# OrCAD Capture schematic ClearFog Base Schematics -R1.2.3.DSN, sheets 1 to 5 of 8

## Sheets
1 BOM Extraction: title: BOM Extraction; rev: 1.0
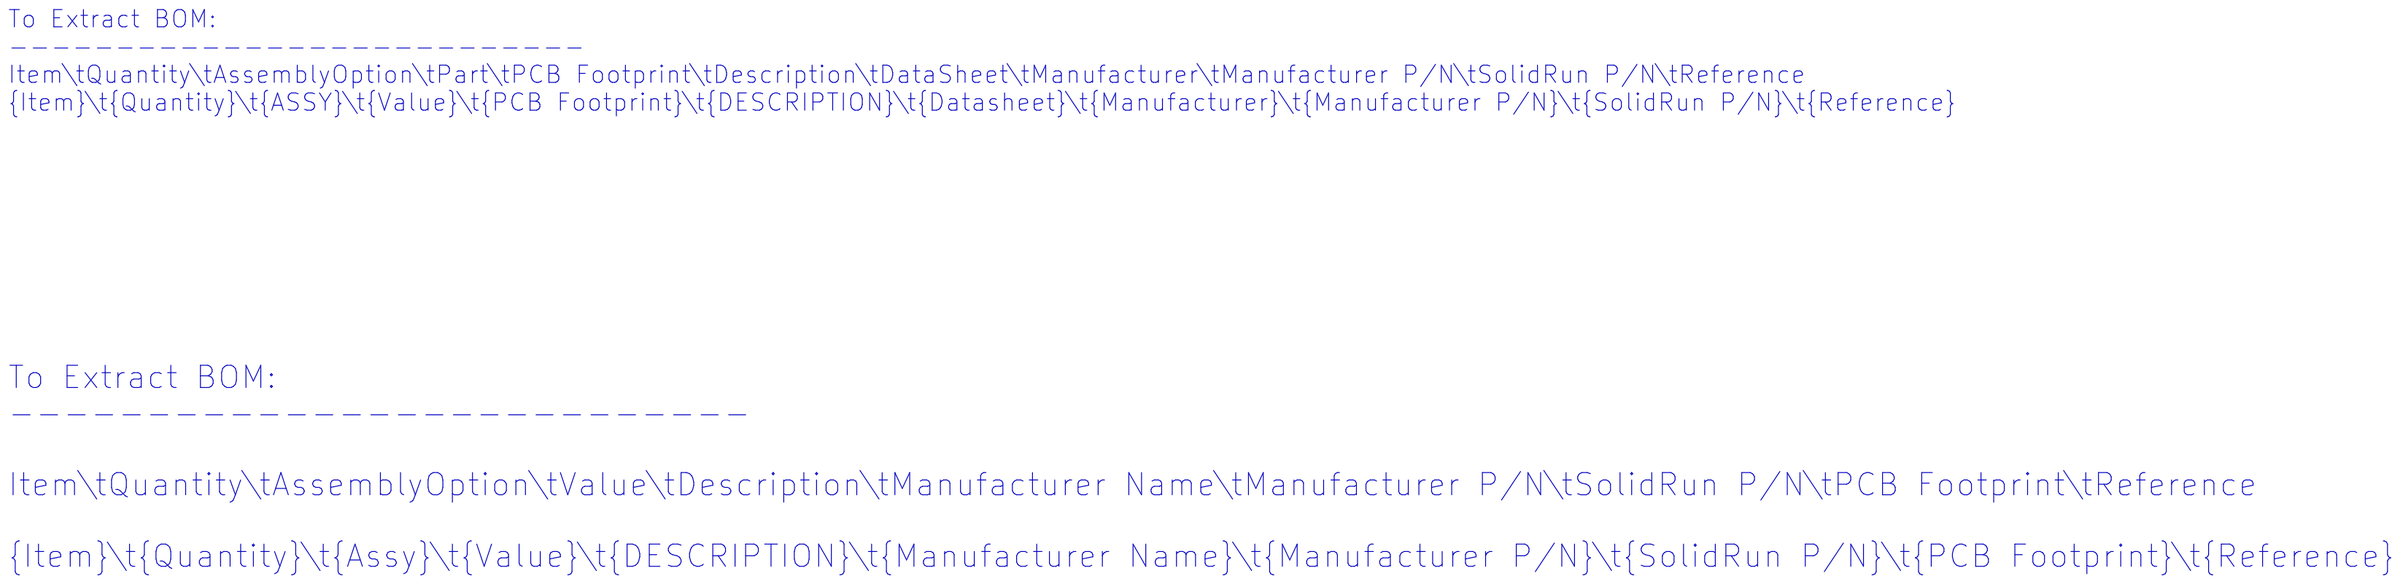
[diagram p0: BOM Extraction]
2 uSOM B2B + Connectivity: size C; title: uSOM B2B + Connectivity
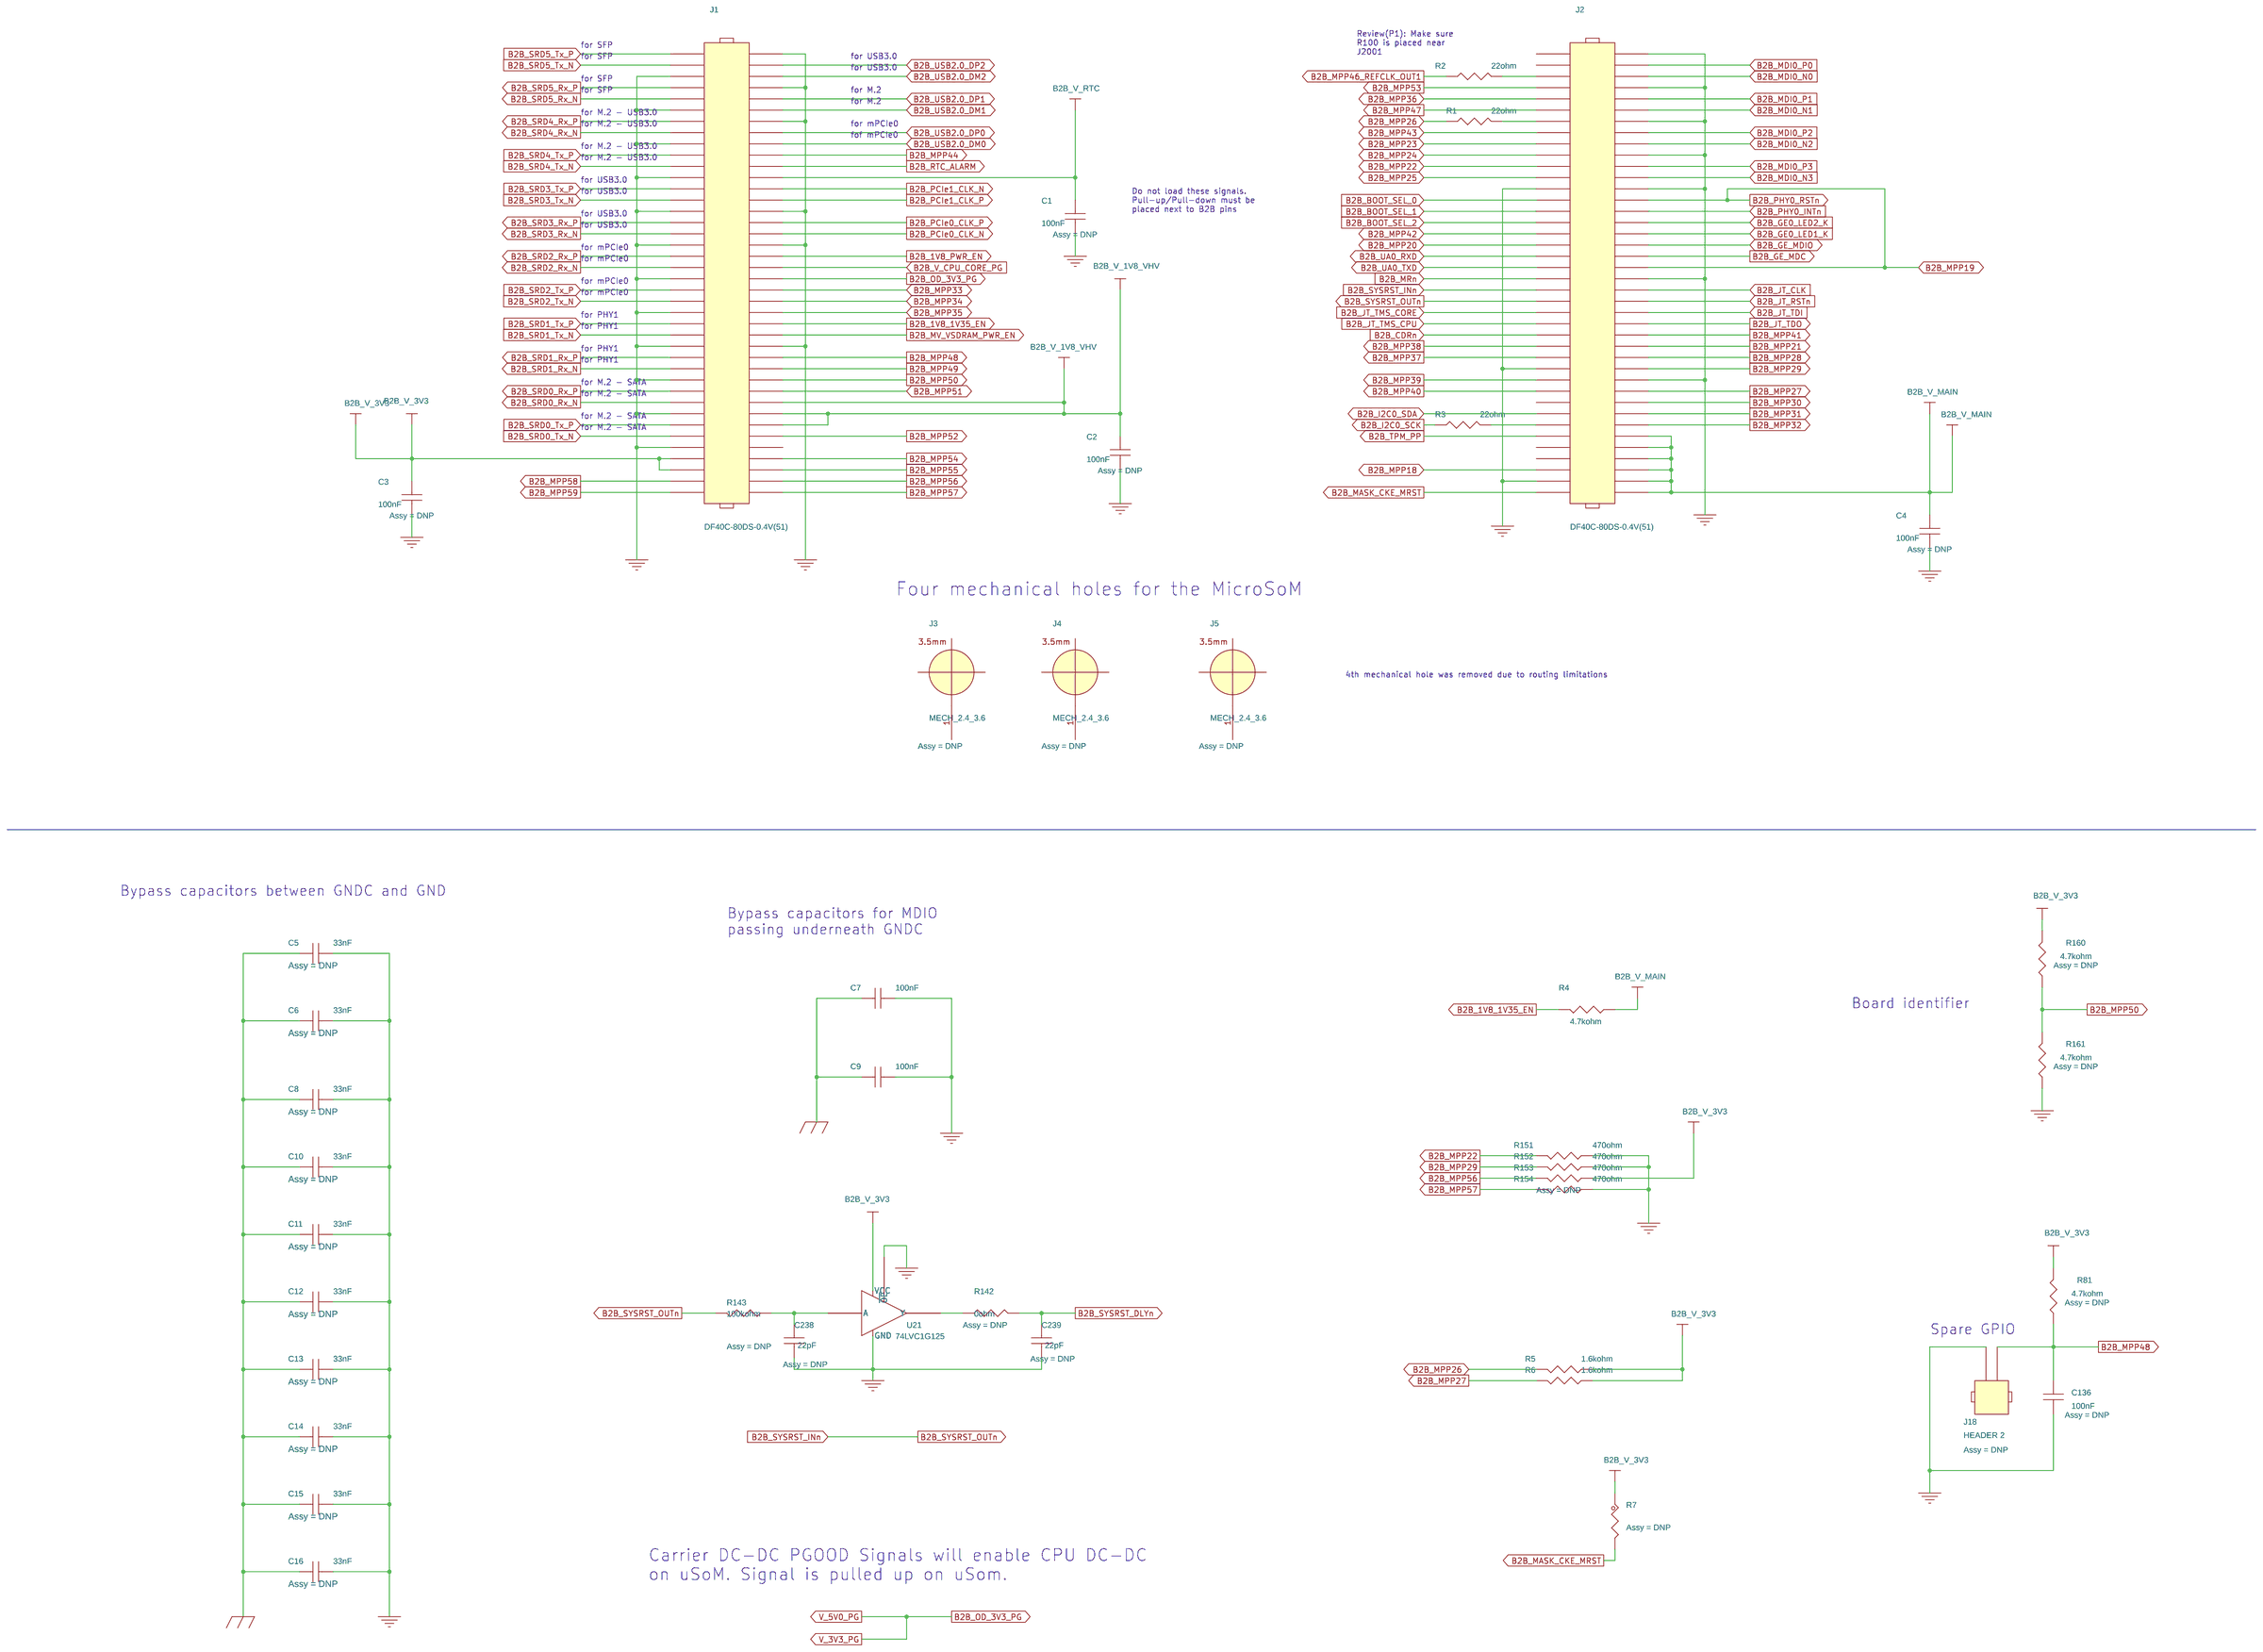
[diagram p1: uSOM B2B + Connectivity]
3 Power: size C; title: Power
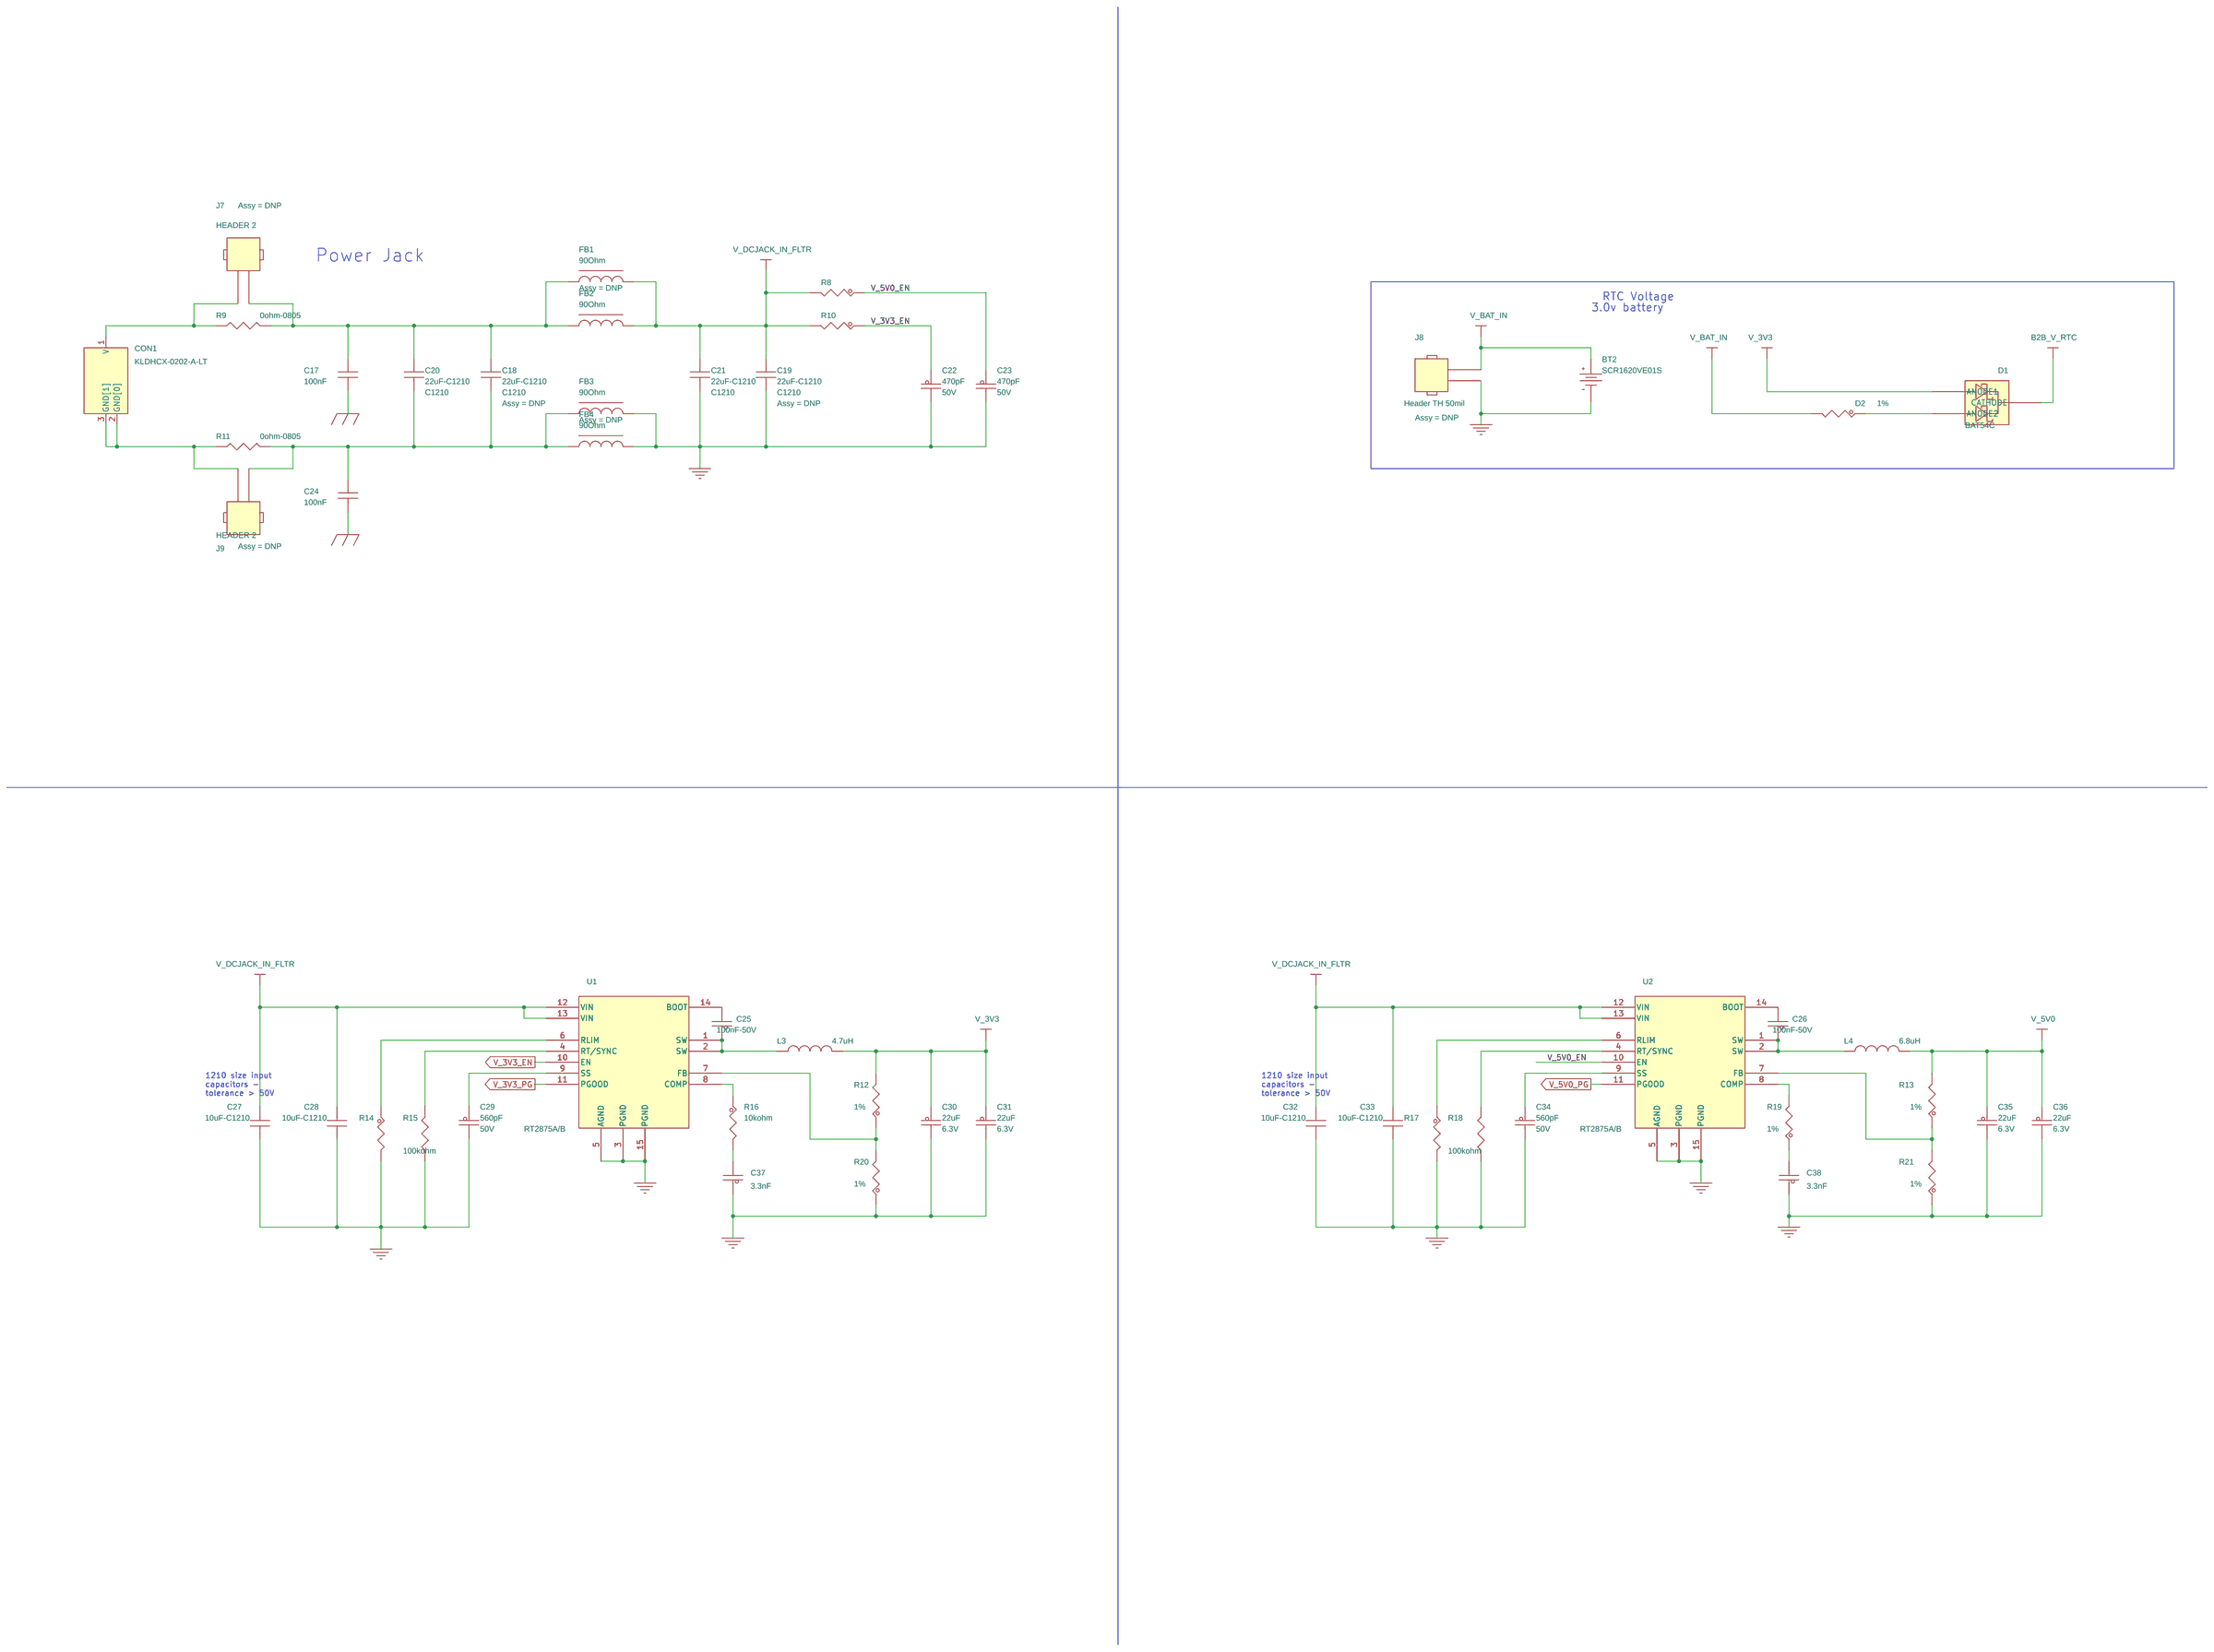
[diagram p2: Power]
4 uSD + USB3.0: size C; title: uSD + USB3.0
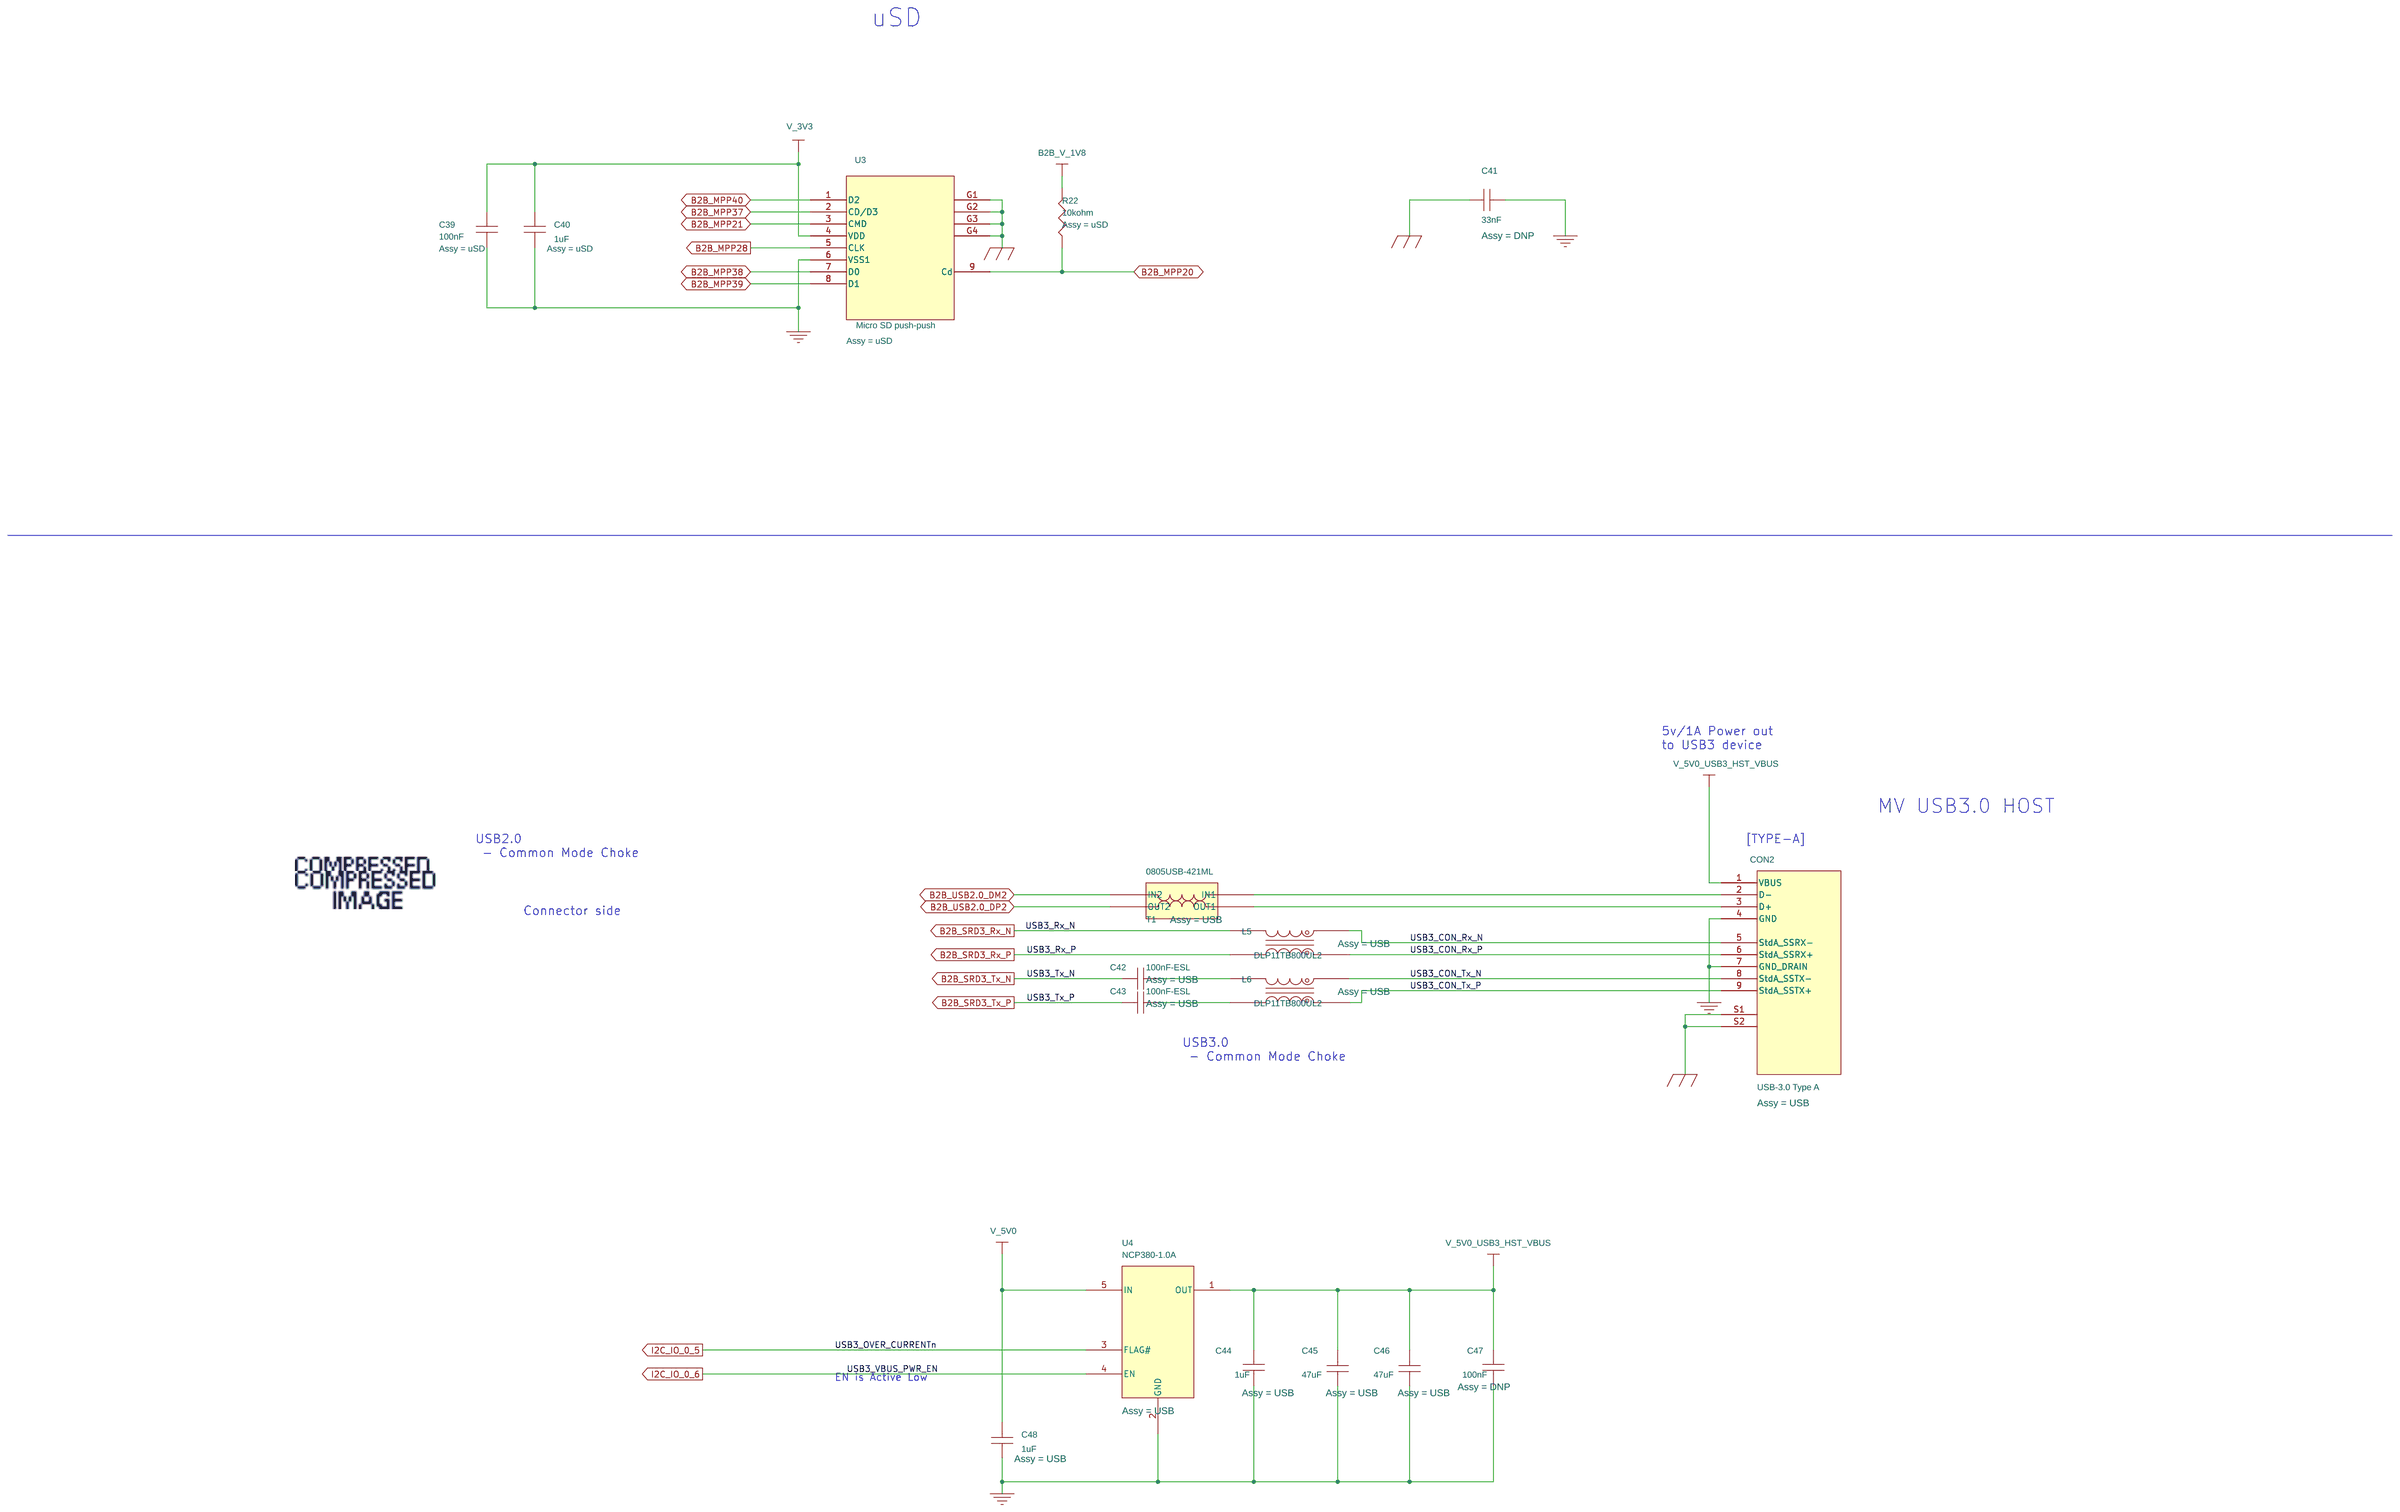
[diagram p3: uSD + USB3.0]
5 mPCIe0 + M.2: size C; title: mPCIe + M.2
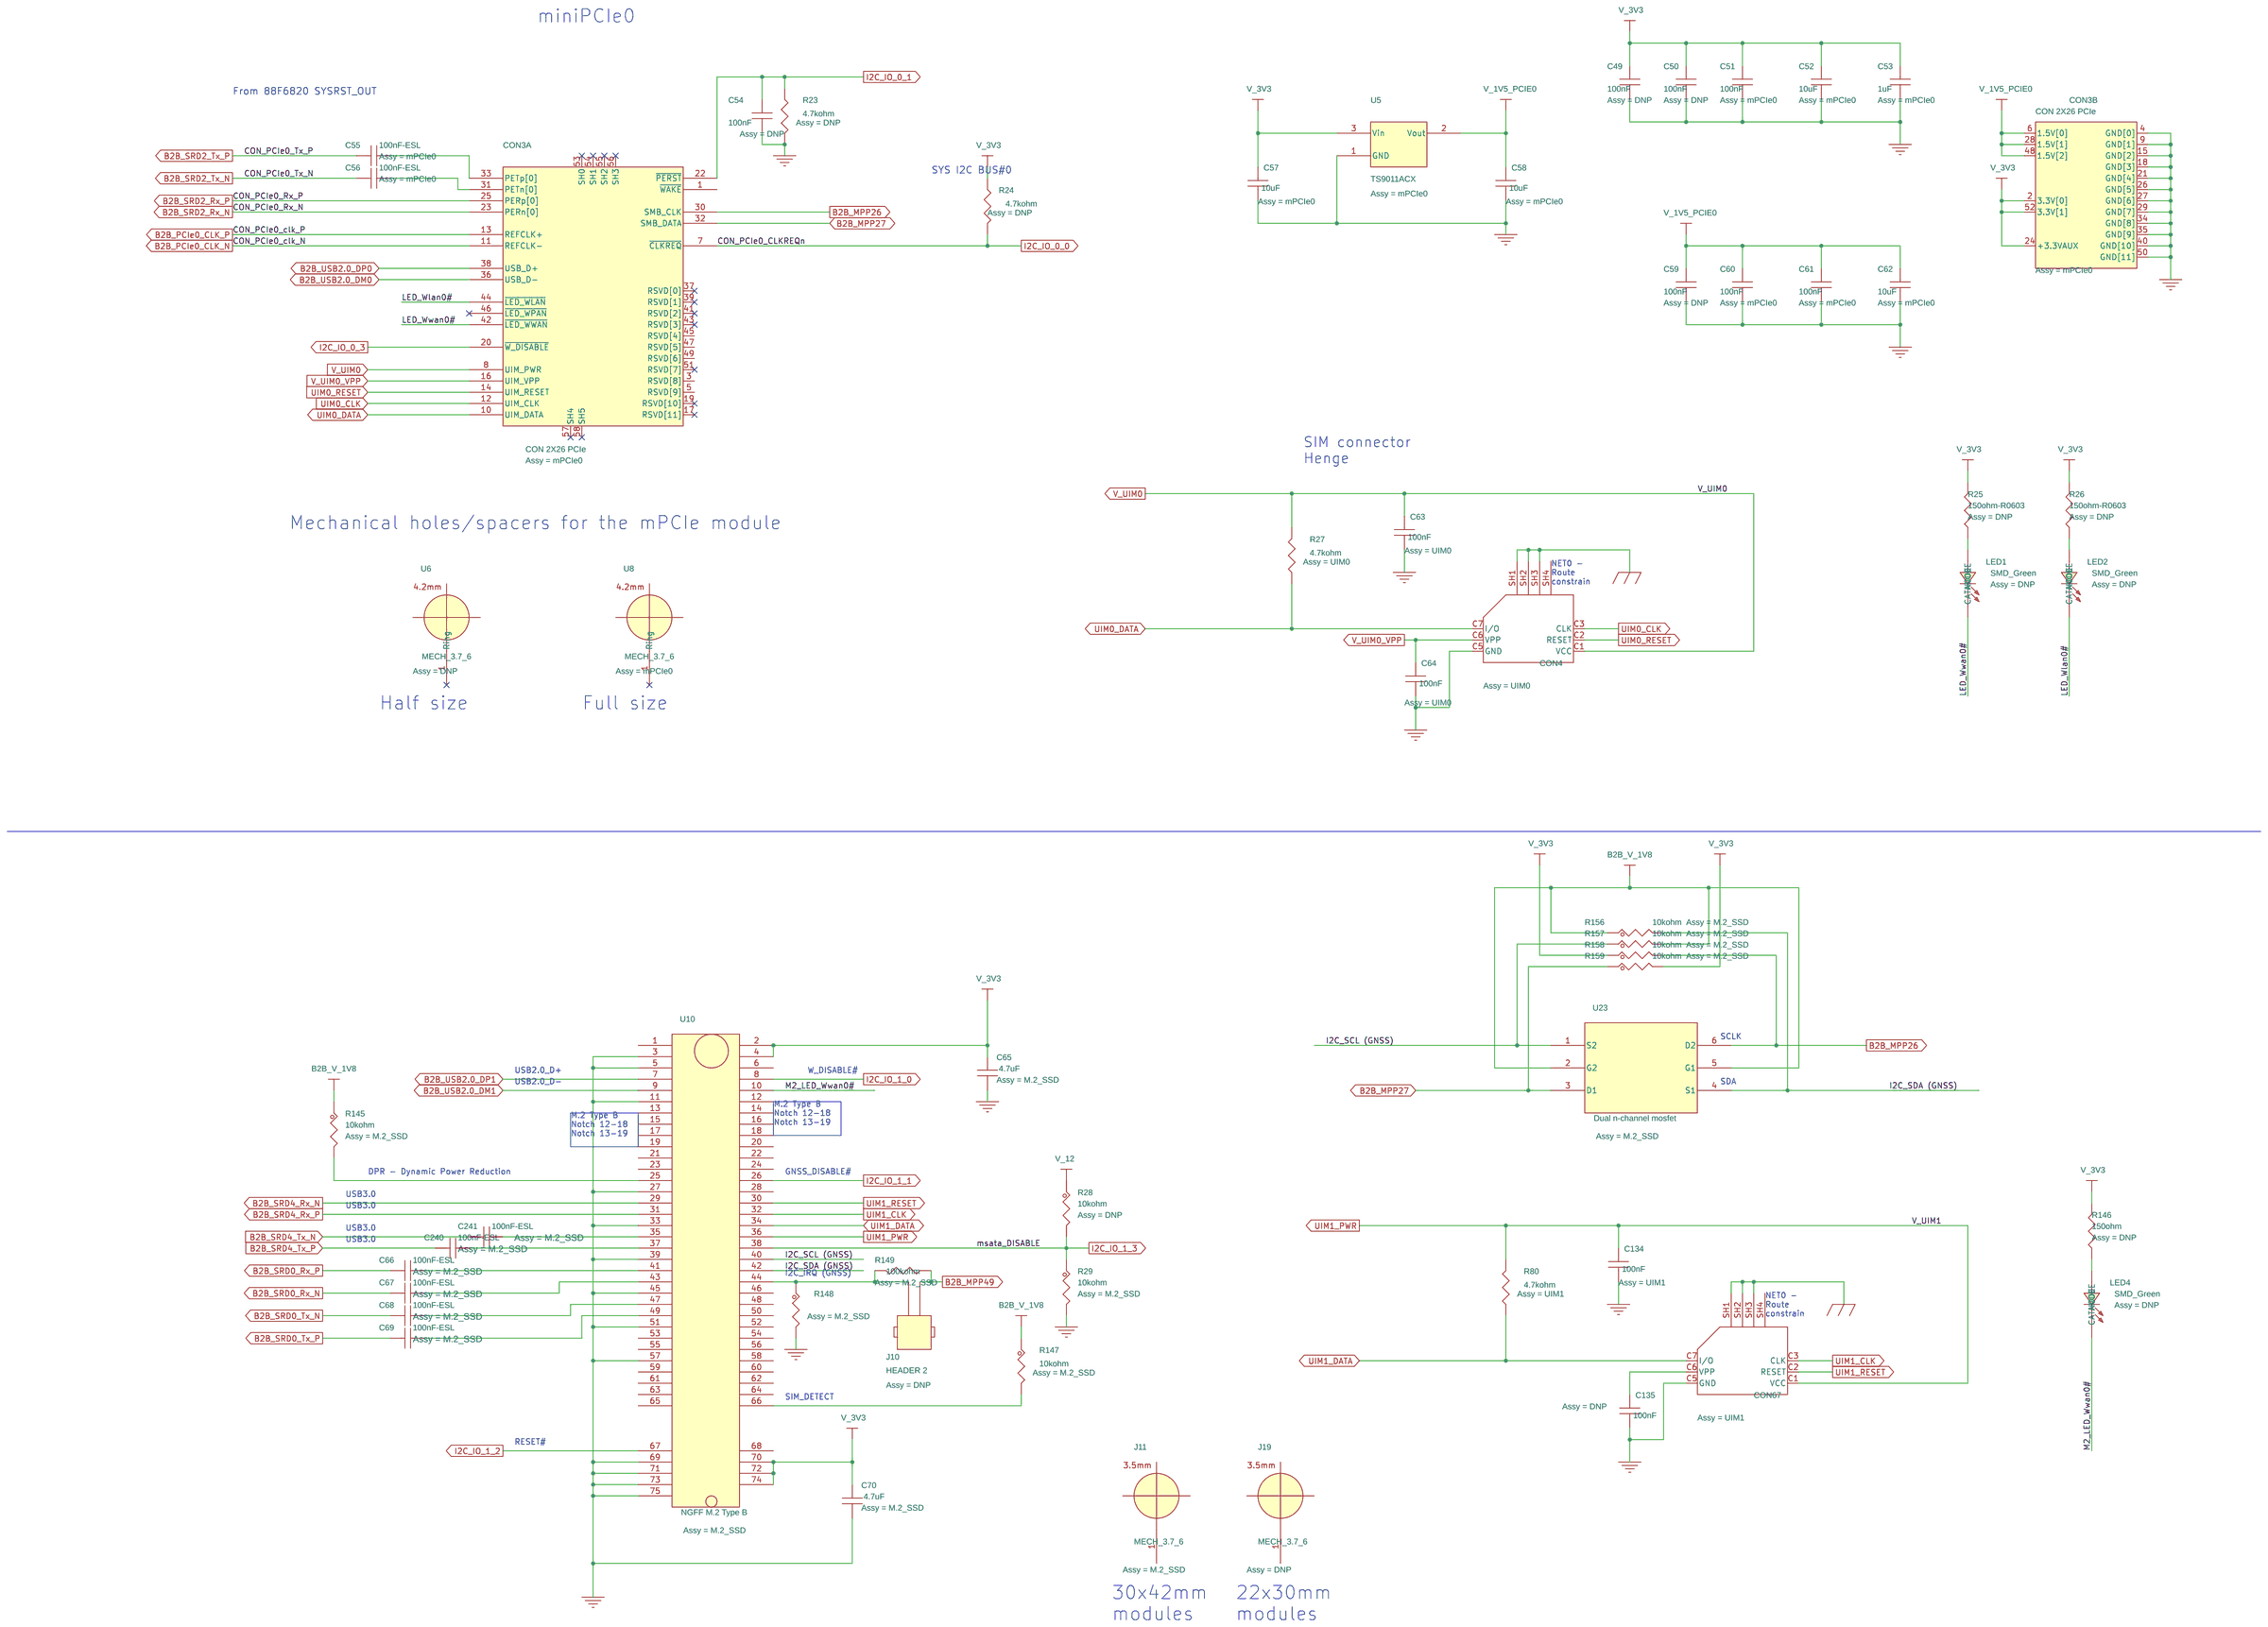
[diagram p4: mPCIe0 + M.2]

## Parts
sheet mPCIe0 + M.2
C49  100nF  [C0402]
C50  100nF  [C0402]
C51  100nF  [C0402]
C52  10uF  [C0603]
C53  1uF  [C0402]
C54  100nF  [C0402]
C55  100nF-ESL  [C0402]
C56  100nF-ESL  [C0402]
C57  10uF  [C0603]
C58  10uF  [C0603]
C59  100nF  [C0402]
C60  100nF  [C0402]
C61  100nF  [C0402]
C62  10uF  [C0603]
C63  100nF  [C0402]
C64  100nF  [C0402]
C65  4.7uF  [C0603]
C66  100nF-ESL  [C0402]
C67  100nF-ESL  [C0402]
C68  100nF-ESL  [C0402]
C69  100nF-ESL  [C0402]
C70  4.7uF  [C0603]
C134  100nF  [C0402]
C135  100nF  [C0402]
C240  100nF-ESL  [C0402]
C241  100nF-ESL  [C0402]
CON3  CON 2X26 PCIe  [AAA-PCI-098]  (sections A,B)
CON4  Micro SIM
CON67  Micro SIM
J10  HEADER 2  [2x100mil]
J11  MECH_3.7_6  [MECH_3.7_6.0]
J19  MECH_3.7_6  [MECH_3.7_6.0]
LED1  SMT Green  [1SA0603]
LED2  SMT Green  [1SA0603]
LED4  SMT Green  [1SA0603]
R23  4.7kohm  [R0402]
R24  4.7kohm  [R0402]
R25  150ohm-R0603  [R0603]
R26  150ohm-R0603  [R0603]
R27  4.7kohm  [R0402]
R28  10kohm  [R0402]
R29  10kohm  [R0402]
R80  4.7kohm  [R0402]
R145  10kohm  [R0402]
R146  150ohm  [R0603]
R147  10kohm  [R0402]
R148  110kohm  [R0402]
R149  100kohm  [R0402]
R156  10kohm  [R0402]
R157  10kohm  [R0402]
R158  10kohm  [R0402]
R159  10kohm  [R0402]
U5  TS9011ACX  [SOT-23]
U6  MECH_3.7_6  [MECH_3.7_6.0]
U8  MECH_3.7_6  [MECH_3.7_6.0]
U10  NGFF M.2 Type B  [NGFF]
U23  Dual n-channel mosfet
sheet Power
BT2  SCR1620VE01S  [N/A]
C17  100nF  [C0402]
C18  22uF-C1210  [C1210]
C19  22uF-C1210  [C1210]
C20  22uF-C1210  [C1210]
C21  22uF-C1210  [C1210]
C22  470pF  [C0402]
C23  470pF  [C0402]
C24  100nF  [C0402]
C25  100nF-50V  [C0402]
C26  100nF-50V  [C0402]
C27  10uF-C1210  [C1210]
C28  10uF-C1210  [C1210]
C29  560pF  [C0402]
C30  22uF  [C0603]
C31  22uF  [C0603]
C32  10uF-C1210  [C1210]
C33  10uF-C1210  [C1210]
C34  560pF  [C0402]
C35  22uF  [C0603]
C36  22uF  [C0603]
C37  3.3nF  [C0402]
C38  3.3nF  [C0402]
CON1  KLDHCX-0202-A-LT
D1  BAT54C  [SOT23-1A3C-DIOD]
D2  25.5kohm  [R0402]
FB1  90Ohm  [L0805]
FB2  90Ohm  [L0805]
FB3  90Ohm  [L0805]
FB4  90Ohm  [L0805]
J7  HEADER 2  [2x100mil]
J8  Header TH 50mil
J9  HEADER 2  [2x100mil]
L3  4.7uH  [SDB0650]
L4  6.8uH  [SDB0650]
R8  110kohm  [R0402]
R9  0ohm-0805  [R0805]
R10  110kohm  [R0402]
R11  0ohm-0805  [R0805]
R12  115kohm  [R0402]
R13  110kohm  [R0402]
R14  50kohm  [R0402]
R15  100kohm  [R0402]
R16  10kohm  [R0402]
R17  50kohm  [R0402]
R18  100kohm  [R0402]
R19  15kohm  [R0402]
R20  25.5kohm  [R0402]
R21  15kohm  [R0402]
U1  RT2875A/B  [TSSOP-14]
U2  RT2875A/B  [TSSOP-14]
sheet uSD + USB3.0
C39  100nF  [C0402]
C40  1uF  [C0402]
C41  33nF  [C0402]
C42  100nF-ESL  [C0402]
C43  100nF-ESL  [C0402]
C44  1uF  [C0402]
C45  47uF  [C1206]
C46  47uF  [C1206]
C47  100nF  [C0402]
C48  1uF  [C0402]
CON2  USB-3.0 Type A  [U3F09D-F1N2]
L5  DLP11TB800UL2  [DLP11TB800UL2]
L6  DLP11TB800UL2  [DLP11TB800UL2]
R22  10kohm  [R0402]
T1  0805USB-421ML  [CHOKE_0805]
U3  Micro SD push-push  [ZM90]
U4  NCP380-1.0A  [TSOP-5]
sheet uSOM B2B + Connectivity
C1  100nF  [C0402]
C2  100nF  [C0402]
C3  100nF  [C0402]
C4  100nF  [C0402]
C5  33nF  [C0402]
C6  33nF  [C0402]
C7  100nF  [C0402]
C8  33nF  [C0402]
C9  100nF  [C0402]
C10  33nF  [C0402]
C11  33nF  [C0402]
C12  33nF  [C0402]
C13  33nF  [C0402]
C14  33nF  [C0402]
C15  33nF  [C0402]
C16  33nF  [C0402]
C136  100nF  [C0402]
C238  22pF  [C0402]
C239  22pF  [C0402]
J1  DF40C-80DS-0.4V(51)  [DF40C-80]
J2  DF40C-80DS-0.4V(51)  [DF40C-80]
J3  MECH_2.4_3.6  [MECH_3.5_4.2]
J4  MECH_2.4_3.6  [MECH_3.5_4.2]
J5  MECH_2.4_3.6  [MECH_3.5_4.2]
J18  HEADER 2  [2x100mil]
R1  22ohm  [R0402]
R2  22ohm  [R0402]
R3  22ohm  [R0402]
R4  4.7kohm  [R0402]
R5  1.6kohm  [R0402]
R6  1.6kohm  [R0402]
R7  100kohm  [R0402]
R81  4.7kohm  [R0402]
R142  0ohm  [R0402]
R143  100kohm  [R0402]
R151  470ohm  [R0402]
R152  470ohm  [R0402]
R153  470ohm  [R0402]
R154  470ohm  [R0402]
R160  4.7kohm  [R0402]
R161  4.7kohm  [R0402]
U21  74LVC1G125  [SOT-353-1]

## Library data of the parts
C49 C50 = Cap: CAP CER 0402 100nF 10V 10% X7R; Assy: DNP; FPLIST: 0402_SQR21,0402_RND,0402; Manufacturer: samsung; Manufacturer Name: samsung; Manufacturer P/N: CL05B104KP5NNNC; Package: 0603; Part Number: C1040402-X7R-16V; SolidRun P/N: CA20001; Updated: 2016-02-10 17:13:33; Datasheet: <null>
C51 = Cap: CAP CER 0402 100nF 10V 10% X7R; Assy: mPCIe0; FPLIST: 0402_SQR21,0402_RND,0402; Manufacturer: samsung; Manufacturer Name: samsung; Manufacturer P/N: CL05B104KP5NNNC; Package: 0603; Part Number: C1040402-X7R-16V; SolidRun P/N: CA20001; Updated: 2016-02-10 17:13:33; Datasheet: <null>
C52 C57 C58 C62 = Cap: CAP CER 0603 10UF 6.3V 10% X5R; Assy: mPCIe0; Manufacturer: Samsung; Manufacturer Name: Samsung; Manufacturer P/N: CL10A106KQ8NNNC; Part Number: C1060805-X5R-16V; SolidRun P/N: CA30001; Updated: 2016-02-10 17:13:33; Datasheet: <null>
C53 = Cap: CAP CER 0402 1uF 10V 10% X5R; Assy: mPCIe0; Manufacturer: samsung; Manufacturer Name: samsung; Manufacturer P/N: CL05A105KP5NNNC; Part Number: C1050603-X7R-16V; SolidRun P/N: CA20005; Updated: 2016-02-10 17:13:33; Datasheet: <null>
C1-C4 C47 C54 C59 C135 C136 = Cap: CAP CER 0402 100nF 10V 10% X7R; Assy: DNP; FPLIST: 0402_SQR21,0402_RND,0402; Manufacturer: samsung; Manufacturer Name: samsung; Manufacturer P/N: CL05B104KP5NNNC; Part Number: C1040402-X7R-16V; SolidRun P/N: CA20001; Updated: 2016-02-10 17:13:33; Datasheet: <null>
C55 C56 = Cap: CAP CER 100NF 16V 10% X7R 0402; Assy: mPCIe0; FPLIST: 0402_SQR21,0402_RND,0402; Manufacturer: CAPAX; Manufacturer Name: CAPAX; Manufacturer P/N: 0402X104K250SNT; Part Number: 0402X104K250SNT; SolidRun P/N: CA20090; Updated: 2016-02-10 17:13:33; Datasheet: <null>
C60 C61 = Cap: CAP CER 0402 100nF 10V 10% X7R; Assy: mPCIe0; FPLIST: 0402_SQR21,0402_RND,0402; Manufacturer: samsung; Manufacturer Name: samsung; Manufacturer P/N: CL05B104KP5NNNC; Part Number: C1040402-X7R-16V; SolidRun P/N: CA20001; Updated: 2016-02-10 17:13:33; Datasheet: <null>
C63 C64 = Cap: CAP CER 0402 100nF 10V 10% X7R; Assy: UIM0; FPLIST: 0402_SQR21,0402_RND,0402; Manufacturer: samsung; Manufacturer Name: samsung; Manufacturer P/N: CL05B104KP5NNNC; Part Number: C1040402-X7R-16V; SolidRun P/N: CA20001; Updated: 2016-02-10 17:13:33; Datasheet: <null>
C65 C70 = Cap: CAP CER 0603 4.7UF 10V 10% X5R; Assy: M.2_SSD; Manufacturer: Hitano; Manufacturer Name: Hitano; Manufacturer P/N: 0603B475K160NU; Part Number: C4750805-X5R-25V; SolidRun P/N: CA30003; Updated: 2016-02-10 17:13:33; Datasheet: <null>
C66-C69 C240 C241 = Cap: CAP CER 100NF 16V 10% X7R 0402; Assy: M.2_SSD; FPLIST: 0402_SQR21,0402_RND,0402; Manufacturer: CAPAX; Manufacturer Name: CAPAX; Manufacturer P/N: 0402X104K250SNT; Part Number: 0402X104K250SNT; SolidRun P/N: CA20090; Updated: 2016-02-10 17:13:33; Datasheet: <null>
C134 = Cap: CAP CER 0402 100nF 10V 10% X7R; Assy: UIM1; FPLIST: 0402_SQR21,0402_RND,0402; Manufacturer: samsung; Manufacturer Name: samsung; Manufacturer P/N: CL05B104KP5NNNC; Part Number: C1040402-X7R-16V; SolidRun P/N: CA20001; Updated: 2016-02-10 17:13:33; Datasheet: <null>
CON3 = 67910-0002: PCI Express / PCI Connectors; Assy: mPCIe0; Manufacturer: TE; Manufacturer Name: TE; Manufacturer P/N: 2041119-2; SolidRun P/N: CO00536; Updated: 2016-02-10 17:13:33
CON4 = SF7W006S1A_1: Micro SIM Card Connector - Push-Push Type 6 or 8 Pin, SMT, 1.50mm Profile (6-pin); Assy: UIM0; CAD_APPROVED: Yes; HEIGHT: 2.35MM; MFG_NAME01: JAE; MFG_PN01: SF7W006S1AE1000; Manufacturer: JAE; Manufacturer Name: GCT; Manufacturer P/N: SIM7100-6-1-15-00-A; ROHS: Yes; SolidRun P/N: CO00569; Updated: 2016-02-10 17:13:33
CON67 = SF7W006S1A_1: Micro SIM Card Connector - Push-Push Type 6 or 8 Pin, SMT, 1.50mm Profile (6-pin); Assy: UIM1; CAD_APPROVED: Yes; HEIGHT: 2.35MM; MFG_NAME01: JAE; MFG_PN01: SF7W006S1AE1000; Manufacturer: JAE; Manufacturer Name: GCT; Manufacturer P/N: SIM7100-6-1-15-00-A; ROHS: Yes; SolidRun P/N: CO00569; Updated: 2016-02-10 17:13:33
J7 J9 J10 J18 = HEADER_2: Two pin through hole header. 100 mil spacing; Assy: DNP; Manufacturer Name: <null>; Manufacturer P/N: <null>; SolidRun P/N: CO00049; Tolerance: <null>; Updated: 2016-02-10 17:13:33; Datasheet: <null>
J11 = MECH_4.5_4: 1.5mm metal spacer for M.2 connector 3.5mm / 5.1mm (3.7mm / 6.0mm hole); Assy: M.2_SSD; Manufacturer: Wurth Elektronik; Manufacturer Name: Wurth Elektronik; Manufacturer P/N: WE 977-401-515-1R; PRIORITY_PN: MCH0008; SolidRun P/N: MCH0008; Tolerance: <null>; Updated: 2016-02-10 17:13:33; Datasheet: http://katalog.we-online.de/em/datasheet/9774015151R.pdf
J19 = MECH_4.5_4: 1.5mm metal spacer for M.2 connector 3.5mm / 5.1mm (3.7mm / 6.0mm hole); Assy: DNP; Manufacturer: Wurth Elektronik; Manufacturer Name: Wurth Elektronik; Manufacturer P/N: WE 977-401-515-1R; PRIORITY_PN: MCH0008; SolidRun P/N: MCH0008; Tolerance: <null>; Updated: 2016-02-10 17:13:33; Datasheet: http://katalog.we-online.de/em/datasheet/9774015151R.pdf
LED1 LED2 LED4 = LED: Indication LED 0603 - Green; Assy: DNP; Colour: SMD_Green; Manufacturer: BRIGHTEK; Manufacturer Name: BRIGHTEK; Manufacturer P/N: 1SA0603G32A0CB01; Part Number: 19-21SYGC/S530-E1/TR8; SolidRun P/N: DI00008; Updated: 2016-02-10 17:13:33; Datasheet: 1SA0603A11A0CC01.pdf
R23 R24 R81 R160 R161 = Resistor: RES 0402 1/16W 4.7K? 1%; Assy: DNP; FPLIST: 0402_SQR21,0402_RND,0402; Manufacturer: Yageo; Manufacturer Name: Yageo; Manufacturer P/N: RC0402FR-074K7L; Part Number: R4720402-1%; SolidRun P/N: RE20002; Updated: 2016-02-10 17:13:33; Datasheet: <null>
R25 R26 = Resistor: CHIP RES 150 1% 1/10W 0603; Assy: DNP; Manufacturer: Yageo; Manufacturer Name: Yageo; Manufacturer P/N: RC0603FR-07150RL; Part Number: R1510603-1%; SolidRun P/N: RE30002; Tolerance: 1%; Updated: 2016-02-10 17:13:33
R27 = Resistor: RES 0402 1/16W 4.7K? 1%; Assy: UIM0; FPLIST: 0402_SQR21,0402_RND,0402; Manufacturer: Yageo; Manufacturer Name: Yageo; Manufacturer P/N: RC0402FR-074K7L; Part Number: R4720402-1%; SolidRun P/N: RE20002; Updated: 2016-02-10 17:13:33; Datasheet: <null>
R28 = RES: RES 0402 1/16W 10K? 1%; Assy: DNP; FPLIST: RC0402_25,RC0402_HD,0402_CC; MFG_NAME01: VISHAY INTERTECHNOLOGY; MFG_PN01: CRCW040210K0FKED; Manufacturer: Yageo; Manufacturer Name: Yageo; Manufacturer P/N: RC0402FR-0710KL; PRIORITY_PN: RE20013; ROHS: Yes; SIGNAL_MODEL: DEFAULT_RESISTOR_10000OHM_2_1; SolidRun P/N: RE20013; Updated: 2016-02-10 17:13:33; Datasheet: <null>
R29 R145 R147 R156-R159 = RES: RES 0402 1/16W 10K? 1%; Assy: M.2_SSD; FPLIST: RC0402_25,RC0402_HD,0402_CC; MFG_NAME01: VISHAY INTERTECHNOLOGY; MFG_PN01: CRCW040210K0FKED; Manufacturer: Yageo; Manufacturer Name: Yageo; Manufacturer P/N: RC0402FR-0710KL; PRIORITY_PN: RE20013; ROHS: Yes; SIGNAL_MODEL: DEFAULT_RESISTOR_10000OHM_2_1; SolidRun P/N: RE20013; Updated: 2016-02-10 17:13:33; Datasheet: <null>
R80 = Resistor: RES 0402 1/16W 4.7K? 1%; Assy: UIM1; FPLIST: 0402_SQR21,0402_RND,0402; Manufacturer: Yageo; Manufacturer Name: Yageo; Manufacturer P/N: RC0402FR-074K7L; Part Number: R4720402-1%; SolidRun P/N: RE20002; Updated: 2016-02-10 17:13:33; Datasheet: <null>
R146 = Resistor: Thick Film Resistors - SMD 150 OHM 5%; Assy: DNP; Manufacturer: Yageo; Manufacturer Name: Yageo; Manufacturer P/N: RC0402JR-07150RL; Part Number: R1510603-1%; SolidRun P/N: RE20014; Tolerance: 1%; Updated: 2016-02-10 17:13:33
R148 = RES: RES 0402 1/16W 110K 1%; Assy: M.2_SSD; CAD_APPROVED: Yes; FPLIST: RC0402_25,RC0402_HD,0402_CC; Manufacturer: Yageo; Manufacturer Name: Yageo; Manufacturer P/N: RC0402FR-07110KL; ROHS: Yes; SIGNAL_MODEL: DEFAULT_RESISTOR_21000OHM_2_1; SolidRun P/N: RE20152; Tolerance: 1%; Updated: 2016-02-10 17:13:33
R149 = Resistor: RES MF 100.0K 1/16W 1% 0402; Assy: M.2_SSD; Manufacturer: Yageo; Manufacturer P/N: RC0402FR-07100KL; Part Number: R1040402-1%; SolidRun P/N: RE20015; Updated: 2015-02-17 20:35:06; Datasheet: <null>
U5 = MC70L15_TO3_0: LDO - 1.5V output, 0.25A, 12V maximum inout; Assy: mPCIe0; Manufacturer: OnSemi; Manufacturer Name: Taiwan Semiconductors; PRIORITY_PN: IC00601; SolidRun P/N: IC00161; Tolerance: <null>; Updated: 2016-02-10 17:13:33; Datasheet: http://www.onsemi.com/pub_link/Collateral/NCP1117-D.PDF
U6 = MECH_2.2_5: 1.5mm metal spacer for M.2 connector 3.5mm / 5.1mm (3.7mm / 6.0mm hole); Assy: DNP; Manufacturer: Wurth Elektronik; Manufacturer Name: Wurth Elektronik; Manufacturer P/N: WE 977-401-515-1R; PRIORITY_PN: MCH0008; SolidRun P/N: MCH0008; Tolerance: <null>; Updated: 2016-02-10 17:13:33; Datasheet: http://katalog.we-online.de/em/datasheet/9774015151R.pdf
U8 = MECH_2.2_5: 1.5mm metal spacer for M.2 connector 3.5mm / 5.1mm (3.7mm / 6.0mm hole); Assy: mPCIe0; Manufacturer: Wurth Elektronik; Manufacturer Name: Wurth Elektronik; Manufacturer P/N: WE 977-401-515-1R; PRIORITY_PN: MCH0008; SolidRun P/N: MCH0008; Tolerance: <null>; Updated: 2016-02-10 17:13:33; Datasheet: http://katalog.we-online.de/em/datasheet/9774015151R.pdf
U10 = NGFF_M.2: NGFF M.2 connector - 3.0H Key B; Assy: M.2_SSD; Manufacturer Name: <null>; Manufacturer P/N: <null>; SolidRun P/N: CO00595; Tolerance: <null>; Updated: 2016-02-10 17:13:33; Datasheet: <null>
U23 = Dual_n-channel_mosfet_1: Dual channel MOSFET Transistor; Assy: M.2_SSD; MFG_NAME01: Diodes; MFG_PN01: DMN65D8LDW-7; SolidRun P/N: IC00023; Datasheet: http://www.diodes.com/datasheets/DMN65D8LDW.pdf
BT2 = Battery_1: <null>; Manufacturer: JL Worldwide; Manufacturer Name: JL Worldwide; PRIORITY_PN: BT00001; SolidRun P/N: BT00001; Tolerance: <null>; Updated: 2016-02-10 17:13:33
C7 C9 C17 C24 = Cap: CAP CER 0402 100nF 10V 10% X7R; Manufacturer: samsung; Manufacturer Name: samsung; Manufacturer P/N: CL05B104KP5NNNC; Part Number: C1040402-X7R-16V; SolidRun P/N: CA20001; Updated: 2016-02-10 17:13:33; Datasheet: <null>
C18 C19 = Cap: CAP CER 22UF 50V 20% X5R 1210; Assy: DNP; Manufacturer Name: SAMSUNG; Manufacturer P/N: CL32B226KBJNNWE; Note: 6.3V; Part Number: C2260805-X5R-6.3V; Price: 0.039; SolidRun P/N: CA60003; Source: Mouser; Source P/N: 810-C2012X5R0J226M-3; Updated: 2016-02-10 17:13:33
C20 C21 = Cap: CAP CER 22UF 50V 20% X5R 1210; Manufacturer Name: SAMSUNG; Manufacturer P/N: CL32B226KBJNNWE; Note: 6.3V; Part Number: C2260805-X5R-6.3V; Price: 0.039; SolidRun P/N: CA60003; Source: Mouser; Source P/N: 810-C2012X5R0J226M-3; Updated: 2016-02-10 17:13:33
C22 C23 = CAP_NP: CAP CER 470PF 50V 10% X7R 0402; CAD_APPROVED: Yes; FPLIST: CC0402_25,CC0402_HD,0402_CC; HEIGHT: 0.55MM; MFG_NAME01: MURATA; MFG_PN01: GRM155R71H471KA01D; Manufacturer: MURATA; Manufacturer Name: MURATA; Manufacturer P/N: GRM155R71H471KA01D; PRIORITY_PN: CA20082; ROHS: Yes; ROOM: RGMII_PHY; SIGNAL_MODEL: DEFAULT_CAPACITOR_470pF_2_1; SolidRun P/N: CA20082; Updated: 2016-02-10 17:13:33; VOLTAGE: 50V; WVDC: 50V; Datasheet: <null>
C25 C26 = CAP_NP: CAP CER 0.1UF 50V 10% X7R 0402; CAD_APPROVED: Yes; Manufacturer: MURATA; Manufacturer Name: MURATA; Manufacturer P/N: GRM155R71H104KE14D; PRIORITY_PN: CA20147; Part Number: GRM155R71H104KE14D; ROHS: Yes; SIGNAL_MODEL: DEFAULT_CAPACITOR_100000pF_2_1; SolidRun P/N: CA20147; Updated: 2016-02-10 17:13:33; VOLTAGE: 50V; WVDC: 50V; Datasheet: <null>
C27 C28 C32 C33 = Cap: CHIP CAP 1210 10uF 50V 20% X5R; Manufacturer Name: Samsung; Manufacturer P/N: CL32B106KBJNNWE; SolidRun P/N: CA60004; Updated: 2016-02-10 17:13:33
C29 C34 = CAP_NP: CAP CER 560PF 50V 10% X7R 0402; CAD_APPROVED: Yes; FPLIST: CC0402_25,CC0402_HD,0402_CC; HEIGHT: 0.55MM; MFG_NAME01: MURATA; MFG_PN01: GRM155R71H561KA01D; Manufacturer: MURATA; Manufacturer Name: MURATA; Manufacturer P/N: GRM155R71H561KA01D; PRIORITY_PN: CA20015; ROHS: Yes; SIGNAL_MODEL: DEFAULT_CAPACITOR_560pF_2_1; SolidRun P/N: CA20015; Updated: 2016-02-10 17:13:33; VOLTAGE: 50V; WVDC: 50V
C30 C31 C35 C36 = CAP_NP: CAP CER 22UF 6.3V 20% X5R 0603; CAD_APPROVED: Yes; FPLIST: CC0603_OV,CC0603,0603_CC; HEIGHT: 1MM; MFG_NAME01: Samsung; MFG_PN01: CL10A226MQ8NRNE; Manufacturer: MURATA; Manufacturer Name: MURATA; Manufacturer P/N: GRM21BR60J226ME39L; PRIORITY_PN: CA30002; ROHS: Yes; SIGNAL_MODEL: DEFAULT_CAPACITOR_2.2e+07pF_2_1; SolidRun P/N: CA30002; Updated: 2016-02-10 17:13:33; VOLTAGE: 6.3V; WVDC: 6.3V
C37 C38 = CAP_NP: CAP CER 3.3nF 16V 10% X5R 0402; CAD_APPROVED: Yes; FPLIST: CC0402_25,CC0402_HD,0402_CC; HEIGHT: 0.635MM; Manufacturer: TDK; Manufacturer Name: TDK; Manufacturer P/N: CGJ2B2X7R1C332K050BA; ROHS: Yes; SIGNAL_MODEL: DEFAULT_CAPACITOR_100000pF_2_1; SolidRun P/N: CA20092; Updated: 2016-02-10 17:13:33; VOLTAGE: 16V; WVDC: 16V
CON1 = POWER_JACK: Power Jack; Manufacturer: Kycon; Manufacturer Name: Kycon; Part Number: KLDX-0202-B-LT; SolidRun P/N: CO00053; Updated: 2016-02-10 17:13:33
D1 = BAT54C: Manufacturer: Vishay; Manufacturer Name: Vishay; Manufacturer P/N: BAT54C-G3-08; Part Number: BAT54C-7-F; SolidRun P/N: DI00001; Updated: 2016-02-10 17:13:33; Datasheet: https://www.fairchildsemi.com/datasheets/BA/BAT54.pdf
D2 R20 = RES: RES 0402 1/16W 25.5K 1%; CAD_APPROVED: Yes; FPLIST: RC0402_25,RC0402_HD,0402_CC; Manufacturer: Yageo; Manufacturer Name: Yageo; Manufacturer P/N: RC0402FR-0725K5L; ROHS: Yes; SIGNAL_MODEL: DEFAULT_RESISTOR_21000OHM_2_1; SolidRun P/N: RE20156; Tolerance: 1%; Updated: 2016-02-10 17:13:33
FB1 FB3 = Ferrite_Bead: Filter Bead 90ohms 25%; Assy: DNP; Manufacturer: VIKING; Manufacturer Name: VIKING; Manufacturer P/N: CB05YTYH900; Notes: 120 Ohm; Part Number: CIS21J121NE; Price: 0.04; SolidRun P/N: IN00001; Source: Mouser; Source P/N: 70-ILHB0805ER900V; Updated: 2016-02-10 17:13:33; Datasheet: http://www.viking.com.tw/ftp/CB.pdf
FB2 FB4 = Ferrite_Bead: Filter Bead 90ohms 25%; Manufacturer: VIKING; Manufacturer Name: VIKING; Manufacturer P/N: CB05YTYH900; Notes: 120 Ohm; Part Number: CIS21J121NE; Price: 0.04; SolidRun P/N: IN00001; Source: Mouser; Source P/N: 70-ILHB0805ER900V; Updated: 2016-02-10 17:13:33; Datasheet: http://www.viking.com.tw/ftp/CB.pdf
J8 = HEADER_2_SM: <null>; Assy: DNP; Manufacturer Name: <null>; Manufacturer P/N: <null>; PRIORITY_PN: CO00105; SolidRun P/N: CO00105; Tolerance: <null>; Updated: 2016-02-10 17:13:33; Datasheet: <null>
L3 = INDUCTOR_2: Power inductor 4.7uH Isat=7A; MFG_NAME01: VIKING; MFG_PN01: SDB0650MT4R7; Manufacturer: VIKING; Manufacturer Name: VIKING; Manufacturer P/N: SDB0650M4R7; PRIORITY_PN: IN00045; SolidRun P/N: IN00045; Updated: 2016-02-10 17:13:33; Datasheet: www.viking.com.tw/ftp/SDB.pdf
L4 = INDUCTOR_2: Power inductor 6.8uH Isat=5.5A; MFG_NAME01: VIKING; MFG_PN01: SDB0650MT6R8; Manufacturer: VIKING; Manufacturer Name: VIKING; Manufacturer P/N: SDB0650M6R8; PRIORITY_PN: IN00047; SolidRun P/N: IN00047; Updated: 2016-02-10 17:13:33; Datasheet: www.viking.com.tw/ftp/SDB.pdf
R8 R10 R13 = RES: RES 0402 1/16W 110K 1%; CAD_APPROVED: Yes; FPLIST: RC0402_25,RC0402_HD,0402_CC; Manufacturer: Yageo; Manufacturer Name: Yageo; Manufacturer P/N: RC0402FR-07110KL; ROHS: Yes; SIGNAL_MODEL: DEFAULT_RESISTOR_21000OHM_2_1; SolidRun P/N: RE20152; Tolerance: 1%; Updated: 2016-02-10 17:13:33
R9 R11 = Resistor: RES 0805 1/8W 0 5%; Manufacturer: Yageo; Manufacturer Name: Yageo; Manufacturer P/N: RC0805JR-070RL; SolidRun P/N: RE40001; Updated: 2016-02-10 17:13:33; Datasheet: <null>
R12 = RES: RES 0402 1/16W 115K 1%; CAD_APPROVED: Yes; FPLIST: RC0402_25,RC0402_HD,0402_CC; Manufacturer: Yageo; Manufacturer Name: Yageo; Manufacturer P/N: RC0402FR-07115KL; ROHS: Yes; SIGNAL_MODEL: DEFAULT_RESISTOR_21000OHM_2_1; SolidRun P/N: RE20153; Tolerance: 1%; Updated: 2016-02-10 17:13:33
R14 R17 = RES: RES MF 50K 1/16W 1% 0402; CAD_APPROVED: Yes; FPLIST: RC0402_25,RC0402_HD,0402_CC; Manufacturer: Yageo; Manufacturer Name: Yageo; Manufacturer P/N: RC0402FR-0750KL; ROHS: Yes; SIGNAL_MODEL: DEFAULT_RESISTOR_21000OHM_2_1; SolidRun P/N: RE20155; Updated: 2016-02-10 17:13:33
R15 R18 = Resistor: RES MF 100.0K 1/16W 1% 0402; Manufacturer: Yageo; Manufacturer Name: Yageo; Manufacturer P/N: RC0402FR-07100KL; Part Number: R1040402-1%; SolidRun P/N: RE20015; Updated: 2016-02-10 17:13:33; Datasheet: <null>
R16 = RES: RES 0402 1/16W 10K? 1%; CAD_APPROVED: Yes; FPLIST: RC0402_25,RC0402_HD,0402_CC; MFG_NAME01: VISHAY INTERTECHNOLOGY; MFG_PN01: CRCW040210K0FKED; Manufacturer: Yageo; Manufacturer Name: Yageo; Manufacturer P/N: RC0402FR-0710KL; PRIORITY_PN: RE20013; ROHS: Yes; SIGNAL_MODEL: DEFAULT_RESISTOR_10000OHM_2_1; SolidRun P/N: RE20013; Updated: 2016-02-10 17:13:33; Datasheet: <null>
R19 R21 = RES: RES 0402 1/16W 15K 1%; CAD_APPROVED: Yes; FPLIST: RC0402_25,RC0402_HD,0402_CC; Manufacturer: Yageo; Manufacturer Name: Yageo; Manufacturer P/N: RC0402FR-0715KL; ROHS: Yes; SIGNAL_MODEL: DEFAULT_RESISTOR_21000OHM_2_1; SolidRun P/N: RE20100; Tolerance: 1%; Updated: 2016-02-10 17:13:33
U1 U2 = RT2875A_B: DC2DC chip; Manufacturer: RICHTECK; Manufacturer Name: RICHTECK; Manufacturer P/N: RT2875B; SolidRun P/N: IC00566; Updated: 2016-02-10 17:13:33; Datasheet: http://www.richtek.com/download_ds.jsp?p=RT2875A/RT2875B
C39 = Cap: CAP CER 0402 100nF 10V 10% X7R; Assy: uSD; Manufacturer: samsung; Manufacturer Name: samsung; Manufacturer P/N: CL05B104KP5NNNC; Part Number: C1040402-X7R-16V; SolidRun P/N: CA20001; Updated: 2016-02-10 17:13:33; Datasheet: <null>
C40 = Cap: CAP CER 0402 1uF 10V 10% X5R; Assy: uSD; Manufacturer: samsung; Manufacturer Name: samsung; Manufacturer P/N: CL05A105KP5NNNC; Part Number: C1050603-X7R-16V; SolidRun P/N: CA20005; Updated: 2016-02-10 17:13:33; Datasheet: <null>
C5 C6 C8 C10-C16 C41 = Cap: CHIP CAP 33nF 6.3V 0402 X5R; Assy: DNP; MFG_NAME01: SAMSUNG; MFG_PN01: CL05B333KP5NNNC; Manufacturer: Murata; Manufacturer Name: Murata; Manufacturer P/N: GRM155R71A333KA01D; SolidRun P/N: CA20011; Updated: 2016-02-10 17:13:33; Datasheet: <null>
C42 C43 = Cap: CAP CER 100NF 16V 10% X7R 0402; Assy: USB; FPLIST: 0402_SQR21,0402_RND,0402; Manufacturer: CAPAX; Manufacturer Name: CAPAX; Manufacturer P/N: 0402X104K250SNT; Part Number: 0402X104K250SNT; SolidRun P/N: CA20090; Updated: 2016-02-10 17:13:33; Datasheet: <null>
C44 C48 = Cap: CAP CER 0402 1uF 10V 10% X5R; Assy: USB; Manufacturer: samsung; Manufacturer Name: samsung; Manufacturer P/N: CL05A105KP5NNNC; Part Number: C1050603-X7R-16V; SolidRun P/N: CA20005; Updated: 2016-02-10 17:13:33; Datasheet: <null>
C45 C46 = Cap: CAP CER 1206 47UF 6.3V 20% X5R; Assy: USB; Manufacturer: murata; Manufacturer Name: murata; Manufacturer P/N: GRM31CR60J476ME19L; Part Number: GMC31X5R476M10NTLF; SolidRun P/N: CA50001; Updated: 2016-02-10 17:13:33; Datasheet: <null>
CON2 = USB3_2: USB-3.0 Host connector; Assy: USB; Manufacturer: Genesis; Manufacturer Name: Genesis; Manufacturer P/N: USAR-2F09-AB63T1H; Part Number: USAR-2F09-AB63T1H; SolidRun P/N: CO00526; Updated: 2016-02-10 17:13:33; Datasheet: <null>
L5 L6 = CHOKE_CMx2: Common Mode Filters / Chokes 0504 80ohm EMI Suppression Fltr; Assy: USB; Manufacturer: Murata; Manufacturer Name: Murata; Manufacturer P/N: DLP11TB800UL2L; SolidRun P/N: IN00033; Updated: 2016-02-10 17:13:33; Datasheet: http://www.mouser.com/ds/2/281/Murata%20DL_PL%20Series-202927.pdf
R22 = Resistor: RES 0402 1/16W 10K? 1%; Assy: uSD; FPLIST: 0402_SQR21,0402_RND,0402; Manufacturer: Yageo; Manufacturer Name: Yageo; Manufacturer P/N: RC0402FR-0710KL; Part Number: R1030402-1%; SolidRun P/N: RE20013; Updated: 2016-02-10 17:13:33; Datasheet: <null>
T1 = DLW21HN121SQ2: Common Mode Filter USB 2.0; Assy: USB; Manufacturer: Coilcraft; Manufacturer Name: Coilcraft; Manufacturer P/N: 0805USB-421MLC; Part Number: 0805USB-421MLC; SolidRun P/N: IN00016; Updated: 2016-02-10 17:13:33; Datasheet: http://www.mouser.com/ds/2/597/0805usb-463502.pdf
U3 = CJ-WK21923-R6SS6_0: SD/MMC card connector; Assy: uSD; MFG_NAME01: CEN LINK; MFG_PN01: ZM90-15000-0BR1; Manufacturer: CEN LINK; Manufacturer Name: CEN LINK; Manufacturer P/N: ZM90-15000-0BR1; SolidRun P/N: CO00091; Updated: 2016-02-10 17:13:33; Datasheet: ZM90-15000-0BR1-(C).pdf
U4 = NCP380: USB 1A Current limiter; Assy: USB; Manufacturer: OnSemi; Manufacturer Name: OnSemi; Manufacturer P/N: NCP380HSN10AAT1G; SolidRun P/N: IC01003; Tolerance: <null>; Updated: 2016-02-10 17:13:33; Datasheet: http://www.onsemi.com/pub_link/Collateral/NCP380-D.PDF
C238 C239 = Cap: CAP CER 0402 22pF 50V 5% C0G; Assy: DNP; Manufacturer: Murata; Manufacturer P/N: GRM1555C1H220JA01D; Part Number: C2200402-NPO-50V; SolidRun P/N: CA20080; Updated: 2015-02-17 20:35:06; Datasheet: <null>
J1 J2 = HEADER_40x2_SM: Board to Board Receptacle 80 pins; Manufacturer: Hirose; Manufacturer Name: Hirose; SolidRun P/N: CO00017; Updated: 2016-02-10 17:13:33; Datasheet: https://www.hirose.co.jp/cataloge_hp/ed_DF40_20140305.pdf
J3-J5 = MECH_4.5_4: <null>; Assy: DNP; Manufacturer Name: <null>; Manufacturer P/N: <null>; PRIORITY_PN: MCH0007; SolidRun P/N: MCH0007; Tolerance: <null>; Updated: 2016-02-10 17:13:33; Datasheet: <null>
R1-R3 = Resistor: RES MF 22 OHM 1/10W -- 0402; FPLIST: 0402_SQR21,0402_RND,0402; Manufacturer: Yageo; Manufacturer Name: Yageo; Manufacturer P/N: RC0402FR-0722RL; Part Number: R2200402-1%; SolidRun P/N: RE20150; Updated: 2016-02-10 17:13:33
R4 = Resistor: RES 0402 1/16W 4.7K? 1%; FPLIST: 0402_SQR21,0402_RND,0402; Manufacturer: Yageo; Manufacturer Name: Yageo; Manufacturer P/N: RC0402FR-074K7L; Part Number: R4720402-1%; SolidRun P/N: RE20002; Updated: 2016-02-10 17:13:33; Datasheet: <null>
R5 R6 = Resistor: RES 0402 1/16W 1.6K? 1%; FPLIST: 0402_SQR21,0402_RND,0402; Manufacturer: Yageo; Manufacturer Name: Yageo; Manufacturer P/N: RC0402FR-071K6L; Part Number: R4720402-1%; SolidRun P/N: RE20030; Updated: 2016-02-10 17:13:33; Datasheet: <null>
R7 = RES: RES MF 100.0K 1/16W 1% 0402; Assy: DNP; CAD_APPROVED: Yes; FPLIST: RC0402_25,RC0402_HD,0402_CC; MFG_NAME01: YAGEO; MFG_PN01: RC0402FR-0710KL; Manufacturer: Yageo; Manufacturer Name: Yageo; Manufacturer P/N: RC0402FR-07100KL; PRIORITY_PN: RE20013; ROHS: Yes; SIGNAL_MODEL: DEFAULT_RESISTOR_10000OHM_2_1; SolidRun P/N: RE20015; Updated: 2016-02-10 17:13:33; Datasheet: <null>
R142 = Resistor: RES 0402 1/16W 0? 5%; Assy: DNP; Manufacturer: Yageo; Manufacturer P/N: RC0402JR-070RL; Part Number: R0000805; SolidRun P/N: RE20009; Updated: 2015-02-17 20:35:06; Datasheet: <null>
R143 = Resistor: RES MF 100.0K 1/16W 1% 0402; Assy: DNP; Manufacturer: Yageo; Manufacturer P/N: RC0402FR-07100KL; Part Number: R1040402-1%; SolidRun P/N: RE20015; Updated: 2015-02-17 20:35:06; Datasheet: <null>
R151-R153 = Resistor: CHIP RES 470 F 1/16W 0402; FPLIST: 0402_SQR21,0402_RND,0402; Manufacturer: Yageo; Manufacturer Name: Yageo; Manufacturer P/N: RC0402JR-07470RL; Part Number: R4720402-1%; SolidRun P/N: RE20025; Updated: 2016-02-10 17:13:33; Datasheet: <null>
R154 = Resistor: CHIP RES 470 F 1/16W 0402; Assy: DNP; FPLIST: 0402_SQR21,0402_RND,0402; Manufacturer: Yageo; Manufacturer Name: Yageo; Manufacturer P/N: RC0402JR-07470RL; Part Number: R4720402-1%; SolidRun P/N: RE20025; Updated: 2016-02-10 17:13:33; Datasheet: <null>
U21 = 74LVC1G125: Single Channel Bus buffer/line driver; 3-state; Assy: DNP; Manufacturer: NXP; Manufacturer P/N: 74LVC1G125GW; SolidRun P/N: IC01056; Datasheet: http://www.nxp.com/documents/data_sheet/74LVC1G125.pdf

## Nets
GND: BT2.MINUS(NEG) C1.2 C2.2 C3.2 C4.2 C5.2 C6.2 C7.2 C8.2 C9.2 C10.2 C11.2 C12.2 C13.2 C14.2 C15.2 C16.2 C19.2 C21.2 C22.2 C23.2 C27.1 C28.1 C29.2 C30.2 C31.2 C32.1 C33.1 C34.2 C35.2 C36.2 C37.1 C38.1 C39.2 C40.2 C41.2 C44.2 C45.1 C46.1 C47.2 C48.1 C49.2 C50.2 C51.2 C52.2 C53.2 C54.2 C57.2 C58.2 C59.2 C60.2 C61.2 C62.2 C63.2 C64.2 C65.2 C70.2 C134.2 C135.2 C136.2 C238.2 C239.2 CON2.4(GND) CON2.7(GND_DRAIN) CON3.4(GND[0]) CON3.9(GND[1]) CON3.15(GND[2]) CON3.18(GND[3]) CON3.21(GND[4]) CON3.26(GND[5]) CON3.27(GND[6]) CON3.29(GND[7]) CON3.34(GND[8]) CON3.35(GND[9]) CON3.40(GND[10]) CON3.50(GND[11]) CON4.C5(GND) CON67.C5(GND) FB3.2 FB4.2 J1.1 J1.6 J1.7 J1.12 J1.13 J1.18 J1.24 J1.29 J1.30 J1.35 J1.36 J1.42 J1.48 J1.53 J1.54 J1.60 J1.66 J1.72 J2.1 J2.7 J2.13 J2.19 J2.25 J2.26 J2.41 J2.58 J2.59 J2.78 J8.2 J18.1 R14.2 R15.1 R17.2 R18.1 R20.1 R21.1 R23.1 R29.2 R148.2 R151.1 R152.1 R154.1 R161.1 U1.3(PGND) U1.5(AGND) U1.15(PGND) U2.3(PGND) U2.5(AGND) U2.15(PGND) U3.6(VSS1) U4.2(GND) U5.1(GND) U10.3 U10.5 U10.11 U10.27 U10.33 U10.39 U10.45 U10.51 U10.57 U10.69 U10.71 U10.73 U10.75 U21.1(~{OE}) U21.3(GND) ; also on sheet 6 7 8
GNDC: C5.1 C6.1 C7.1 C8.1 C9.1 C10.1 C11.1 C12.1 C13.1 C14.1 C15.1 C16.1 C17.2 C24.2 C41.1 CON2.S1 CON2.S2 CON4.SH1 CON4.SH2 CON4.SH3 CON67.SH1 CON67.SH2 CON67.SH3 U3.G1 U3.G2 U3.G3 U3.G4 ; also on sheet 6 7
VCC: U21.5(VCC) ; also on sheet 8
B2B_1V8_1V35_EN: J1.49 R4.2
B2B_1V8_PWR_EN: J1.37
B2B_BOOT_SEL_0: J2.28 ; also on sheet 8
B2B_BOOT_SEL_1: J2.30 ; also on sheet 8
B2B_BOOT_SEL_2: J2.32 ; also on sheet 8
B2B_CDRn: J2.52
B2B_GE0_LED1_K: J2.33 ; also on sheet 7 8
B2B_GE0_LED2_K: J2.31 ; also on sheet 7 8
B2B_GE_MDC: J2.37 ; also on sheet 7
B2B_GE_MDIO: J2.35 ; also on sheet 7
B2B_I2C0_SCK: R3.1 ; also on sheet 8
B2B_I2C0_SDA: J2.66 ; also on sheet 8
B2B_JT_CLK: J2.43
B2B_JT_RSTn: J2.45
B2B_JT_TDI: J2.47
B2B_JT_TDO: J2.49
B2B_JT_TMS_CORE: J2.48
B2B_JT_TMS_CPU: J2.50
B2B_MASK_CKE_MRST: J2.80 R7.2
B2B_MDI0_N0: J2.5 ; also on sheet 7
B2B_MDI0_N1: J2.11 ; also on sheet 7
B2B_MDI0_N2: J2.17 ; also on sheet 7
B2B_MDI0_N3: J2.23 ; also on sheet 7
B2B_MDI0_P0: J2.3 ; also on sheet 7
B2B_MDI0_P1: J2.9 ; also on sheet 7
B2B_MDI0_P2: J2.15 ; also on sheet 7
B2B_MDI0_P3: J2.21 ; also on sheet 7
B2B_MPP18: J2.76 ; also on sheet 8
B2B_MPP19: J2.27 J2.39 ; also on sheet 7
B2B_MPP20: J2.36 R22.1 U3.9(Cd)
B2B_MPP21: J2.53 U3.3(CMD)
B2B_MPP22: J2.22 R151.2 ; also on sheet 8
B2B_MPP23: J2.18
B2B_MPP24: J2.20 ; also on sheet 8
B2B_MPP25: J2.24 ; also on sheet 8
B2B_MPP26: CON3.30(SMB_CLK) R1.1 R5.2 R158.2 U23.6(D2) ; also on sheet 6 8
B2B_MPP27: CON3.32(SMB_DATA) J2.61 R6.2 R159.1 U23.3(D1) ; also on sheet 6 8
B2B_MPP28: J2.55 U3.5(CLK)
B2B_MPP29: J2.57 R152.2 ; also on sheet 8
B2B_MPP30: J2.63 ; also on sheet 8
B2B_MPP31: J2.65 ; also on sheet 8
B2B_MPP32: J2.67
B2B_MPP33: J1.43 ; also on sheet 8
B2B_MPP34: J1.45 ; also on sheet 8
B2B_MPP35: J1.47 ; also on sheet 8
B2B_MPP36: J2.10
B2B_MPP37: J2.56 U3.2(CD/D3)
B2B_MPP38: J2.54 U3.7(D0)
B2B_MPP39: J2.60 U3.8(D1)
B2B_MPP40: J2.62 U3.1(D2)
B2B_MPP41: J2.51
B2B_MPP42: J2.34 ; also on sheet 8
B2B_MPP43: J2.16 ; also on sheet 8
B2B_MPP44: J1.19 ; also on sheet 8
B2B_MPP46_REFCLK_OUT1: R2.1 ; also on sheet 7
B2B_MPP47: J2.12
B2B_MPP48: C136.1 J1.55 J18.2 R81.1
B2B_MPP49: J1.57 J10.2 R149.1
B2B_MPP50: J1.59 R160.1 R161.2
B2B_MPP51: J1.61
B2B_MPP52: J1.69
B2B_MPP53: J2.8
B2B_MPP54: J1.73 ; also on sheet 8
B2B_MPP55: J1.75
B2B_MPP56: J1.77 R153.2 ; also on sheet 8
B2B_MPP57: J1.79 R154.2 ; also on sheet 8
B2B_MPP58: J1.78 ; also on sheet 8
B2B_MPP59: J1.80
B2B_MRn: J2.42 ; also on sheet 8
B2B_MV_VSDRAM_PWR_EN: J1.51
B2B_OD_3V3_PG: J1.41 U1.11(PGOOD) U2.11(PGOOD)
B2B_PCIe0_CLK_N: CON3.11(REFCLK-) J1.33
B2B_PCIe0_CLK_P: CON3.13(REFCLK+) J1.31
B2B_PCIe1_CLK_N: J1.25
B2B_PCIe1_CLK_P: J1.27
B2B_PHY0_INTn: J2.29
B2B_RTC_ALARM: J1.21
B2B_SRD0_Rx_N: C67.2 J1.64
B2B_SRD0_Rx_P: C66.2 J1.62
B2B_SRD0_Tx_N: C68.2 J1.70
B2B_SRD0_Tx_P: C69.2 J1.68
B2B_SRD1_Rx_N: J1.58 ; also on sheet 7
B2B_SRD1_Rx_P: J1.56 ; also on sheet 7
B2B_SRD1_Tx_N: J1.52 ; also on sheet 7
B2B_SRD1_Tx_P: J1.50 ; also on sheet 7
B2B_SRD2_Rx_N: CON3.23(PERn[0]) J1.40
B2B_SRD2_Rx_P: CON3.25(PERp[0]) J1.38
B2B_SRD2_Tx_N: C56.2 J1.46
B2B_SRD2_Tx_P: C55.2 J1.44
B2B_SRD3_Rx_N: J1.34 L5.3
B2B_SRD3_Rx_P: J1.32 L5.2
B2B_SRD3_Tx_N: C42.2 J1.28
B2B_SRD3_Tx_P: C43.2 J1.26
B2B_SRD4_Rx_N: J1.16 U10.29
B2B_SRD4_Rx_P: J1.14 U10.31
B2B_SRD4_Tx_N: C241.2 J1.22
B2B_SRD4_Tx_P: C240.2 J1.20
B2B_SRD5_Rx_N: J1.10 ; also on sheet 6
B2B_SRD5_Rx_P: J1.8 ; also on sheet 6
B2B_SRD5_Tx_N: J1.4 ; also on sheet 6
B2B_SRD5_Tx_P: J1.2 ; also on sheet 6
B2B_SYSRST_DLYn: C239.1 R142.2 ; also on sheet 8
B2B_SYSRST_INn: J2.44 J2.46 R143.2
B2B_TPM_PP: J2.70 ; also on sheet 8
B2B_UA0_RXD: J2.38 ; also on sheet 6
B2B_UA0_TXD: J2.40 ; also on sheet 6
B2B_USB2.0_DM0: CON3.36(USB_D-) J1.17
B2B_USB2.0_DM1: J1.11 U10.9
B2B_USB2.0_DM2: J1.5 T1.2(IN2)
B2B_USB2.0_DP0: CON3.38(USB_D+) J1.15
B2B_USB2.0_DP1: J1.9 U10.7
B2B_USB2.0_DP2: J1.3 T1.3(OUT2)
B2B_V_1V8: C2.1 J1.63 J1.65 J1.67 R22.2 R145.1 R147.1 R156.1 R157.2 U23.2(G2) U23.5(G1) ; also on sheet 7 8
B2B_V_3V3: C3.1 C30.1 C31.1 C39.1 C40.1 C49.1 C50.1 C51.1 C52.1 C53.1 C57.1 C65.1 C70.1 CON3.2(3.3V[0]) CON3.24(+3.3VAUX) CON3.52(3.3V[1]) D1.1(ANODE1) J1.74 J1.76 L3.2 R5.1 R6.1 R7.1 R12.2 R24.2 R25.2 R26.2 R28.1 R81.2 R146.2 R153.1 R158.1 R159.2 R160.2 U3.4(VDD) U5.3(Vin) U10.2 U10.4 U10.70 U10.72 U10.74 ; also on sheet 6 7 8
B2B_V_CPU_CORE_PG: J1.39
B2B_V_MAIN: C4.1 C35.1 C36.1 C48.2 J2.69 J2.71 J2.73 J2.75 J2.77 J2.79 L4.2 R4.1 R13.2 U4.5(IN) ; also on sheet 8
B2B_V_RTC: C1.1 D1.3(CATHODE) J1.23
I2C_IO_0_0: CON3.7(~{CLKREQ}) R24.1 ; also on sheet 8
I2C_IO_0_1: C54.1 CON3.22(~{PERST}) R23.2 ; also on sheet 8
I2C_IO_0_3: CON3.20(~{W_DISABLE}) ; also on sheet 8
I2C_IO_0_5: U4.3(FLAG#) ; also on sheet 8
I2C_IO_0_6: U4.4(EN) ; also on sheet 8
I2C_IO_1_0: U10.8 ; also on sheet 8
I2C_IO_1_1: U10.26 ; also on sheet 8
I2C_IO_1_2: U10.67 ; also on sheet 8
I2C_IO_1_3: R28.2 R29.1 U10.38 ; also on sheet 8
I2C_SCL (GNSS): R157.1 U10.40 U23.1(S2)
I2C_SDA (GNSS): R156.2 U10.42 U23.4(S1)
LED_Wlan0#: CON3.44(~{LED_WLAN}) LED2.C(CATHODE)
LED_Wwan0#: CON3.42(~{LED_WWAN}) LED1.C(CATHODE)
M2_LED_Wwan0#: LED4.C(CATHODE) U10.10
UIM0_CLK: CON3.12(UIM_CLK) CON4.C3(CLK)
UIM0_DATA: CON3.10(UIM_DATA) CON4.C7(I/O) R27.1
UIM0_RESET: CON3.14(UIM_RESET) CON4.C2(RESET)
UIM1_CLK: CON67.C3(CLK) U10.32
UIM1_DATA: CON67.C7(I/O) R80.1 U10.34
UIM1_PWR: C134.1 CON67.C1(VCC) R80.2 U10.36
UIM1_RESET: CON67.C2(RESET) U10.30
USB3_CON_Rx_N: CON2.5(StdA_SSRX-) L5.4
USB3_CON_Rx_P: CON2.6(StdA_SSRX+) L5.1
USB3_CON_Tx_N: CON2.8(StdA_SSTX-) L6.4
USB3_CON_Tx_P: CON2.9(StdA_SSTX+) L6.1
V_1V5_pcie0: C58.1 C59.1 C60.1 C61.1 C62.1 CON3.6(1.5V[0]) CON3.28(1.5V[1]) CON3.48(1.5V[2]) U5.2(Vout)
V_3V3_EN: C22.1 R10.1 U1.10(EN)
V_5V0_EN: C23.1 R8.1 U2.10(EN)
V_5V0_USB3_HST_VBUS: C44.1 C45.2 C46.2 C47.1 CON2.1(VBUS) U4.1(OUT)
V_BAT_IN: BT2.PLUS(POS) D2.2 J8.1
V_DCJACK_IN_FLTR: C19.1 C21.1 C27.2 C28.2 C32.2 C33.2 FB1.2 FB2.2 R8.2 R10.2 U1.12(VIN) U1.13(VIN) U2.12(VIN) U2.13(VIN) ; also on sheet 6
V_UIM0: C63.1 CON3.8(UIM_PWR) CON4.C1(VCC) R27.2
V_UIM0_VPP: C64.1 CON3.16(UIM_VPP) CON4.C6(VPP)
N04862: C55.1 CON3.33(PETp[0])
N04870: C56.1 CON3.31(PETn[0])
N16774209: C18.2 C20.2 C24.1 FB3.1 FB4.1 J9.1 R11.2
N16774275: C17.1 C18.1 C20.1 FB1.1 FB2.1 J7.1 R9.2
N16828966: C25.1 L3.1 U1.1(SW) U1.2(SW)
N16829013: R15.2 U1.4(RT/SYNC)
N16829019: R16.1 U1.8(COMP)
N16829023: C37.2 R16.2
N16829041: R12.1 R20.2 U1.7(FB)
N16829087: R14.1 U1.6(RLIM)
N16829093: C29.1 U1.9(SS)
N16832129: C26.1 L4.1 U2.1(SW) U2.2(SW)
N16832180: R18.2 U2.4(RT/SYNC)
N16832186: R19.2 U2.8(COMP)
N16832190: C38.2 R19.1
N16832208: R13.1 R21.2 U2.7(FB)
N16832244: R17.1 U2.6(RLIM)
N16832260: C34.1 U2.9(SS)
N17083111: LED2.A(ANODE) R26.1
N17345970: J2.68 R3.2
N17345998: J2.14 R1.2
N17358833: CON1.2(GND[0]) CON1.3(GND[1]) J9.2 R11.1
N17448466: J2.6 R2.2
N17484360: CON1.1(V) J7.2 R9.1
N17702065: LED1.A(ANODE) R25.1
N17720534: C42.1 L6.3
N17720536: C43.1 L6.2
N17720609: CON2.3(D+) T1.4(OUT1)
N17720613: CON2.2(D-) T1.1(IN1)
N17725531: C66.1 U10.41
N17725533: C67.1 U10.43
N17725543: C68.1 U10.47
N17725549: C69.1 U10.49
N17725841: J10.1 R148.1 R149.2 U10.44
N17786755: C135.1 CON67.C6(VPP)
N17829167: R142.1 U21.4(Y)
N17829174: C238.1 R143.1 U21.2(A)
N17830733: R145.2 U10.25
N17831145: C241.1 U10.35
N17831152: C240.1 U10.37
N17831247: LED4.A(ANODE) R146.1
N17831708: R147.2 U10.66
N17903160: D1.2(ANODE2) D2.1
N17909924: C26.2 U2.14(BOOT)
N17909925: C25.2 U1.14(BOOT)

Not connected (* = marked no-connect by the designer): CON3 1(~{WAKE}) 3(RSVD[8]) 5(RSVD[9]) 17(RSVD[11])* 19(RSVD[10])* 37(RSVD[0])* 39(RSVD[1])* 41(RSVD[2])* 43(RSVD[3])* 45(RSVD[4]) 46(~{LED_WPAN})* 47(RSVD[5]) 49(RSVD[6]) 51(RSVD[7])* 53(SH0)* 54(SH1)* 55(SH2)* 56(SH3)* 57(SH4)* 58(SH5)*; CON4 SH4; CON67 SH4; J1 71; J2 2 4 64 72 74; J3 1; J4 1; J5 1; J11 1; J19 1; U6 1(Ring)*; U8 1(Ring)*; U10 1 6 12 13 14 15 16 17 18 19 20 21 22 23 24 28 46 48 50 52 53 54 55 56 58 59 60 61 62 63 64 65 68

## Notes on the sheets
sheet 1
- To Extract BOM:
  ---------------------------
  Item\tQuantity\tAssemblyOption\tPart\tPCB Footprint\tDescription\tDataSheet\tManufacturer\tManufacturer P/N\tSolidRun P/N\tReference
  {Item}\t{Quantity}\t{ASSY}\t{Value}\t{PCB Footprint}\t{DESCRIPTION}\t{Datasheet}\t{Manufacturer}\t{Manufacturer P/N}\t{SolidRun P/N}\t{Reference}
- To Extract BOM:
  ---------------------------
  Item\tQuantity\tAssemblyOption\tValue\tDescription\tManufacturer Name\tManufacturer P/N\tSolidRun P/N\tPCB Footprint\tReference
  {Item}\t{Quantity}\t{Assy}\t{Value}\t{DESCRIPTION}\t{Manufacturer Name}\t{Manufacturer P/N}\t{SolidRun P/N}\t{PCB Footprint}\t{Reference}
sheet 2
- for SFP
- Review(P1): Make sure
  R100 is placed near
  J2001
- for SFP
- for USB3.0
- for USB3.0
- for SFP
- for SFP
- for M.2
- for M.2
- for M.2 - USB3.0
- for M.2 - USB3.0
- for mPCIe0
- fof mPCIe0
- for M.2 - USB3.0
- for M.2 - USB3.0
- for USB3.0
- for USB3.0
- Do not load these signals.
  Pull-up/Pull-down must be
  placed next to B2B pins
- for USB3.0
- for USB3.0
- for mPCIe0
- for mPCIe0
- for mPCIe0
- for mPCIe0
- for PHY1
- for PHY1
- for PHY1
- for PHY1
- for M.2 - SATA
- for M.2 - SATA
- for M.2 - SATA
- for M.2 - SATA
- Four mechanical holes for the MicroSoM
- 4th mechanical hole was removed due to routing limitations
- Bypass capacitors between GNDC and GND
- Bypass capacitors for MDIO
  passing underneath GNDC
- Board identifier
- Spare GPIO
- Carrier DC-DC PGOOD Signals will enable CPU DC-DC
  on uSoM. Signal is pulled up on uSom.
sheet 3
- Power Jack
- RTC Voltage
- 3.0v battery
- 1210 size input
  capacitors -
  tolerance > 50V
- 1210 size input
  capacitors -
  tolerance > 50V
sheet 4
- uSD
- 5v/1A Power out
  to USB3 device
- MV USB3.0 HOST
- USB2.0
   - Common Mode Choke
- [TYPE-A]
- Connector side
- USB3.0
   - Common Mode Choke
- EN is Active Low
sheet 5
- miniPCIe0
- From 88F6820 SYSRST_OUT
- SYS I2C BUS#0
- SIM connector
  Henge
- Mechanical holes/spacers for the mPCIe module
- NET0 -
  Route
  constrain
- Half size
- Full size
- SCLK
- USB2.0_D+
- W_DISABLE#
- USB2.0_D-
- SDA
- M.2 Type B
  Notch 12-18
  Notch 13-19
- M.2 Type B
  Notch 12-18
  Notch 13-19
- DPR - Dynamic Power Reduction
- GNSS_DISABLE#
- USB3.0
- USB3.0
- USB3.0
- USB3.0
- I2C_IRQ (GNSS)
- NET0 -
  Route
  constrain
- SIM_DETECT
- RESET#
- 30x42mm
  modules
- 22x30mm
  modules
